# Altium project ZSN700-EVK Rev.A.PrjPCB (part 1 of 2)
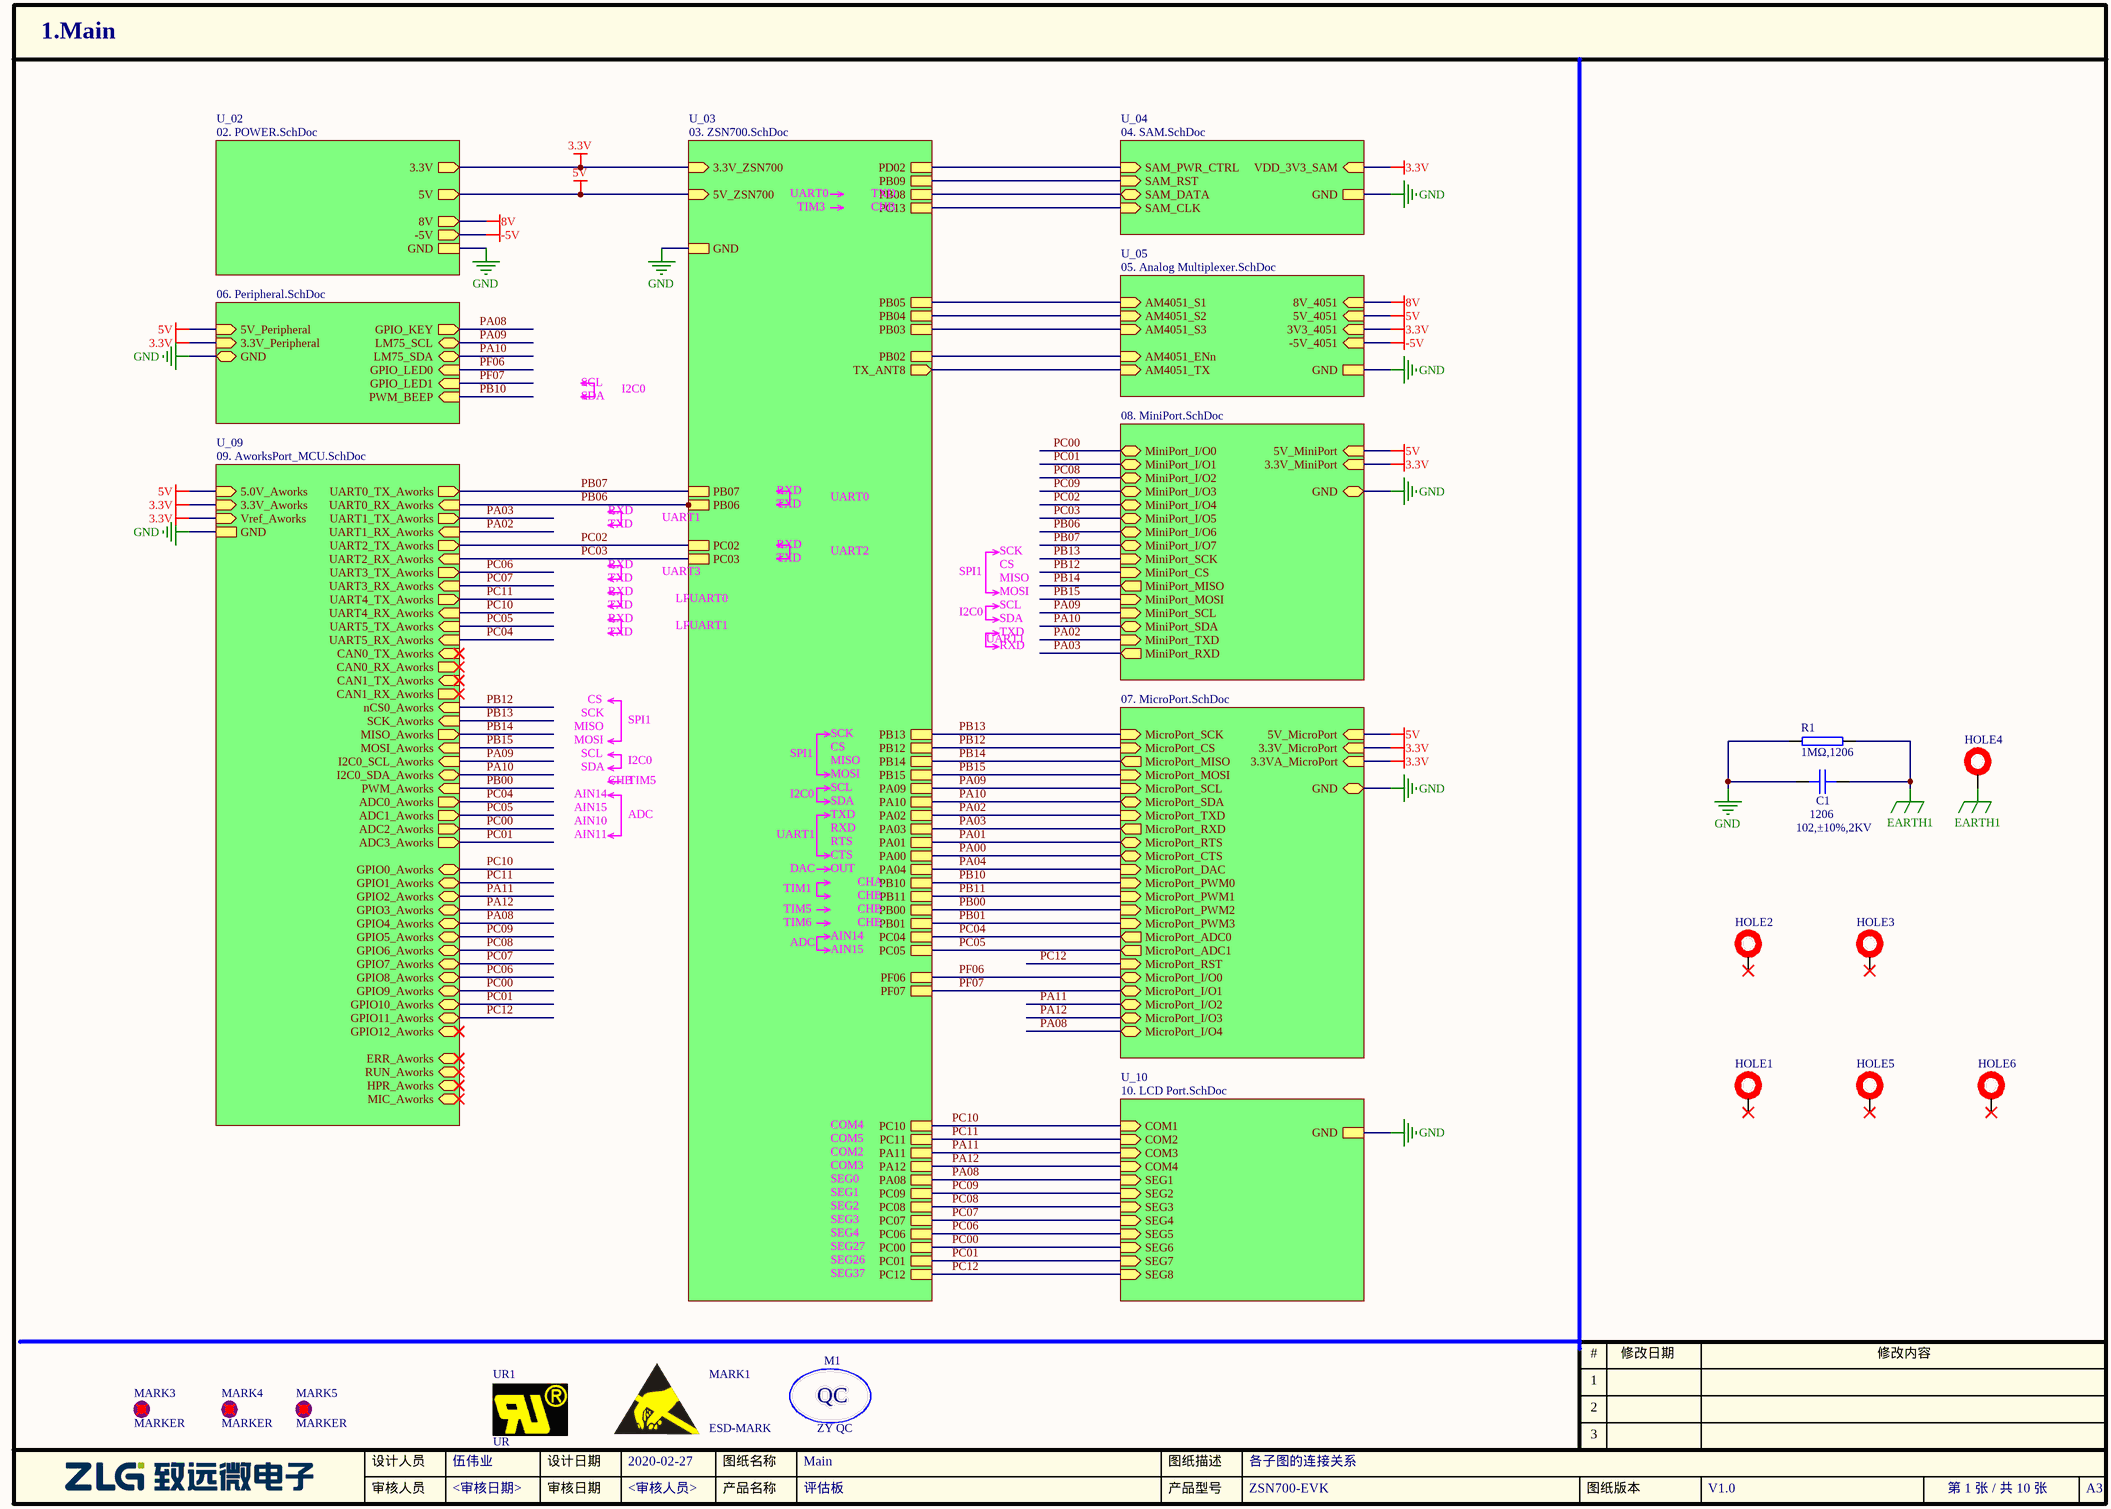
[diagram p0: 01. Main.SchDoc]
productModel: ZSN700-EVK; productName: 评估板
10 sheets, 172 parts. Net scope: hierarchical (ports join the sheet entries above them; power ports are global).
Board file: ZSN700-EVK Rev.A.PcbDoc
Sheets:
  01. Main.SchDoc
    U_03 = 06. Peripheral.SchDoc
    U_05 = 08. MiniPort.SchDoc
    U_06 = 07. MicroPort.SchDoc
    U_03 = 03. ZSN700.SchDoc
    U_02 = 02. POWER.SchDoc
    U_04 = 04. SAM.SchDoc
    U_05 = 05. Analog Multiplexer.SchDoc
    U_10 = 10. LCD Port.SchDoc
    U_09 = 09. AworksPort_MCU.SchDoc

## Sheet 01. Main.SchDoc
size A3; CheckedBy: <审核日期>; Author: 伍伟业; CompanyName: 广州立功科技股份有限公司; DocumentNumber: 1; SheetNumber: 1; SheetTotal: 10; PageSetup: Record=PageOptions¦CenterHorizontal=True¦CenterVertical=True¦PrintScale=1.00¦XCorrection=1.00¦YCorrection=1.00¦PrintKind=0¦BorderSize=5000000¦LeftOffset=0¦BottomOffset=0¦Orientation=2¦PaperLength=1000¦PaperWidth=1000¦Scale=100¦PaperSource=7¦PrintQuality=600¦MediaType=1¦DitherType=10¦PaperKind=A4¦PrintScaleMode=1; DesignDate: 2020-02-27; CheckDate: <审核人员>; SheetName: Main; SheetVersion: V1.0; SheetDescription: 各子图的连接关系

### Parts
C1  封装: 1206  型号: 102,±10%,2KV  [1206C]  (hidden comment: CC1206KKX7RDBB102,102)
HOLE1  (no value)  [HOLE-2.2]  (no BOM)
HOLE2  (no value)  [HOLE-2.2]  (no BOM)
HOLE3  (no value)  [HOLE-2.2]  (no BOM)
HOLE4  (no value)  [HOLE-2.2]  (no BOM)
HOLE5  (no value)  [HOLE-2.2]  (no BOM)
HOLE6  (no value)  [HOLE-2.2]  (no BOM)
M1  ZY QC  [ZY_QC]  (no BOM)
MARK1  ESD-MARK  [ZY_ESD-7]
MARK3  MARKER  [MARKER-C-1.0M]
MARK4  MARKER  [MARKER-C-1.0M]
MARK5  MARKER  [MARKER-C-1.0M]
R1  1MΩ,1206  [1206R]
UR1  UR  [ZY_UR-3X2]

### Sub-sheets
U_02 = 02. POWER.SchDoc: GND, 3.3V (out), 5V (out), 8V (out), -5V (out)
U_03 = 06. Peripheral.SchDoc: GPIO_LED0 (in), GPIO_LED1 (in), PWM_BEEP (in), GPIO_KEY (out), LM75_SCL (bidir), LM75_SDA (bidir), 5V_Peripheral (in), 3.3V_Peripheral (in), GND
U_03 = 03. ZSN700.SchDoc: PC13, PC00, PC01, PC02, PC03, PA00, PA01, PA02, PA03, PA04, PC04, PC05, PB00, PB01, PB02, PB10, PB11, PC08, PC07, PC06, PB15, PB14, PB13, PB12, PA12, PA11, PA10, PA09, PA08, PC09, PC12, PC11, PC10, PF07, PF06, PB07, PB06, PB05, PB04, PB03, PD02, PB08, PB09, 3.3V_ZSN700 (in), GND, TX_ANT8 (out), 5V_ZSN700 (in)
U_04 = 04. SAM.SchDoc: SAM_CLK (in), SAM_DATA (bidir), SAM_RST (in), SAM_PWR_CTRL (in), VDD_3V3_SAM (in), GND
U_05 = 08. MiniPort.SchDoc: MiniPort_SDA (bidir), MiniPort_SCL (in), MiniPort_MOSI (in), MiniPort_SCK (in), MiniPort_I/O3 (bidir), MiniPort_MISO (out), MiniPort_CS (in), MiniPort_I/O0 (bidir), MiniPort_I/O7 (bidir), MiniPort_I/O6 (bidir), MiniPort_I/O5 (bidir), MiniPort_I/O4 (bidir), MiniPort_TXD (in), MiniPort_RXD (out), MiniPort_I/O2 (bidir), MiniPort_I/O1 (bidir), GND, 3.3V_MiniPort (in), 5V_MiniPort (in)
U_05 = 05. Analog Multiplexer.SchDoc: AM4051_S2 (in), AM4051_S1 (in), AM4051_S3 (in), GND, 8V_4051 (in), AM4051_ENn (in), AM4051_TX (in), 3V3_4051 (in), 5V_4051 (in), -5V_4051 (in)
U_06 = 07. MicroPort.SchDoc: MicroPort_RXD (out), MicroPort_TXD (in), MicroPort_CTS (bidir), MicroPort_RTS (bidir), MicroPort_I/O0 (bidir), MicroPort_PWM1 (in), MicroPort_PWM0 (in), MicroPort_RST (in), MicroPort_SCK (in), MicroPort_MISO (out), MicroPort_MOSI (in), MicroPort_CS (in), MicroPort_I/O1 (bidir), MicroPort_PWM3 (in), MicroPort_PWM2 (in), MicroPort_ADC0 (out), MicroPort_ADC1 (out), MicroPort_DAC (in), MicroPort_I/O4 (bidir), MicroPort_SDA (bidir), MicroPort_SCL (in), MicroPort_I/O2 (bidir), MicroPort_I/O3 (bidir), GND, 3.3V_MicroPort (in), 5V_MicroPort (in), 3.3VA_MicroPort (in)
U_09 = 09. AworksPort_MCU.SchDoc: 3.3V_Aworks (in), 5.0V_Aworks (in), GND, Vref_Aworks (in), SCK_Aworks (in), MISO_Aworks (out), RUN_Aworks (bidir), CAN1_RX_Aworks (out), CAN0_RX_Aworks (out), nCS0_Aworks (in), MOSI_Aworks (in), ERR_Aworks (bidir), UART0_TX_Aworks (out), CAN1_TX_Aworks (in), CAN0_TX_Aworks (in), UART1_TX_Aworks (out), UART2_TX_Aworks (out), UART3_TX_Aworks (out), UART4_TX_Aworks (out), UART5_TX_Aworks (in), UART0_RX_Aworks (in), UART1_RX_Aworks (in), UART2_RX_Aworks (in), UART3_RX_Aworks (in), UART4_RX_Aworks (in), UART5_RX_Aworks (in), HPR_Aworks (bidir), MIC_Aworks (bidir), ADC0_Aworks (out), ADC1_Aworks (out), ADC2_Aworks (out), ADC3_Aworks (out), I2C0_SCL_Aworks (in), I2C0_SDA_Aworks (bidir), GPIO0_Aworks (bidir), GPIO1_Aworks (bidir), GPIO2_Aworks (bidir), GPIO3_Aworks (bidir), GPIO4_Aworks (bidir), GPIO5_Aworks (bidir), GPIO6_Aworks (bidir), GPIO7_Aworks (bidir), GPIO8_Aworks (bidir), GPIO9_Aworks (bidir), GPIO10_Aworks (bidir), GPIO11_Aworks (bidir), GPIO12_Aworks (bidir), PWM_Aworks (in)
U_10 = 10. LCD Port.SchDoc: GND, COM1 (in), COM2 (in), COM3 (in), COM4 (in), SEG1 (in), SEG2 (in), SEG3 (in), SEG4 (in), SEG5 (in), SEG6 (in), SEG7 (in), SEG8 (in)

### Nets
3.3V: sheet U_03/3.3V_Peripheral, sheet U_05/3.3V_MiniPort, sheet U_06/3.3V_MicroPort, sheet U_06/3.3VA_MicroPort, sheet U_03/3.3V_ZSN700, sheet U_02/3.3V, sheet U_04/VDD_3V3_SAM, sheet U_05/3V3_4051, sheet U_09/3.3V_Aworks, sheet U_09/Vref_Aworks
5V: sheet U_03/5V_Peripheral, sheet U_05/5V_MiniPort, sheet U_06/5V_MicroPort, sheet U_03/5V_ZSN700, sheet U_02/5V, sheet U_05/5V_4051, sheet U_09/5.0V_Aworks  [project net 5.0V_Aworks]
8V: sheet U_02/8V, sheet U_05/8V_4051
-5V: sheet U_02/-5V, sheet U_05/-5V_4051
EARTH1: C1.1 HOLE4.1 R1.2
GND: C1.2 R1.1 ; sheet U_03/GND, sheet U_05/GND, sheet U_06/GND, sheet U_03/GND, sheet U_02/GND, sheet U_04/GND, sheet U_05/GND, sheet U_10/GND, sheet U_09/GND
AM4051_ENn: sheet U_03/PB02, sheet U_05/AM4051_ENn
AM4051_S1: sheet U_03/PB05, sheet U_05/AM4051_S1
AM4051_S2: sheet U_03/PB04, sheet U_05/AM4051_S2
AM4051_S3: sheet U_03/PB03, sheet U_05/AM4051_S3
AM4051_TX: sheet U_03/TX_ANT8, sheet U_05/AM4051_TX
PA00: sheet U_06/MicroPort_CTS, sheet U_03/PA00  [project net MicroPort_CTS]
PA01: sheet U_06/MicroPort_RTS, sheet U_03/PA01  [project net MicroPort_RTS]
PA02: sheet U_05/MiniPort_TXD, sheet U_06/MicroPort_TXD, sheet U_03/PA02, sheet U_09/UART1_RX_Aworks  [project net MicroPort_TXD]
PA03: sheet U_05/MiniPort_RXD, sheet U_06/MicroPort_RXD, sheet U_03/PA03, sheet U_09/UART1_TX_Aworks  [project net MicroPort_RXD]
PA04: sheet U_06/MicroPort_DAC, sheet U_03/PA04  [project net MicroPort_DAC]
PA08: sheet U_03/GPIO_KEY, sheet U_06/MicroPort_I/O4, sheet U_03/PA08, sheet U_10/SEG1, sheet U_09/GPIO4_Aworks  [project net GPIO4_Aworks]
PA09: sheet U_03/LM75_SCL, sheet U_05/MiniPort_SCL, sheet U_06/MicroPort_SCL, sheet U_03/PA09, sheet U_09/I2C0_SCL_Aworks  [project net I2C0_SCL_Aworks]
PA10: sheet U_03/LM75_SDA, sheet U_05/MiniPort_SDA, sheet U_06/MicroPort_SDA, sheet U_03/PA10, sheet U_09/I2C0_SDA_Aworks  [project net I2C0_SDA_Aworks]
PA11: sheet U_06/MicroPort_I/O2, sheet U_03/PA11, sheet U_10/COM3, sheet U_09/GPIO2_Aworks  [project net COM2]
PA12: sheet U_06/MicroPort_I/O3, sheet U_03/PA12, sheet U_10/COM4, sheet U_09/GPIO3_Aworks  [project net COM3]
PB00: sheet U_06/MicroPort_PWM2, sheet U_03/PB00, sheet U_09/PWM_Aworks  [project net MicroPort_PWM2]
PB01: sheet U_06/MicroPort_PWM3, sheet U_03/PB01  [project net MicroPort_PWM3]
PB06: sheet U_05/MiniPort_I/O6, sheet U_03/PB06, sheet U_09/UART0_RX_Aworks  [project net MiniPort_I/O6]
PB07: sheet U_05/MiniPort_I/O7, sheet U_03/PB07, sheet U_09/UART0_TX_Aworks  [project net MiniPort_I/O7]
PB08: sheet U_03/PB08, sheet U_04/SAM_DATA
PB09: sheet U_03/PB09, sheet U_04/SAM_RST
PB10: sheet U_03/PWM_BEEP, sheet U_06/MicroPort_PWM0, sheet U_03/PB10  [project net MicroPort_PWM0]
PB11: sheet U_06/MicroPort_PWM1, sheet U_03/PB11  [project net MicroPort_PWM1]
PB12: sheet U_05/MiniPort_CS, sheet U_06/MicroPort_CS, sheet U_03/PB12, sheet U_09/nCS0_Aworks  [project net MicroPort_CS]
PB13: sheet U_05/MiniPort_SCK, sheet U_06/MicroPort_SCK, sheet U_03/PB13, sheet U_09/SCK_Aworks  [project net MicroPort_SCK]
PB14: sheet U_05/MiniPort_MISO, sheet U_06/MicroPort_MISO, sheet U_03/PB14, sheet U_09/MISO_Aworks  [project net MicroPort_MISO]
PB15: sheet U_05/MiniPort_MOSI, sheet U_06/MicroPort_MOSI, sheet U_03/PB15, sheet U_09/MOSI_Aworks  [project net MicroPort_MOSI]
PC00: sheet U_05/MiniPort_I/O0, sheet U_03/PC00, sheet U_10/SEG6, sheet U_09/ADC2_Aworks, sheet U_09/GPIO9_Aworks  [project net ADC2_Aworks]
PC01: sheet U_05/MiniPort_I/O1, sheet U_03/PC01, sheet U_10/SEG7, sheet U_09/ADC3_Aworks, sheet U_09/GPIO10_Aworks  [project net ADC3_Aworks]
PC02: sheet U_05/MiniPort_I/O4, sheet U_03/PC02, sheet U_09/UART2_TX_Aworks  [project net MiniPort_I/O4]
PC03: sheet U_05/MiniPort_I/O5, sheet U_03/PC03, sheet U_09/UART2_RX_Aworks  [project net MiniPort_I/O5]
PC04: sheet U_06/MicroPort_ADC0, sheet U_03/PC04, sheet U_09/UART5_RX_Aworks, sheet U_09/ADC0_Aworks  [project net ADC0_Aworks]
PC05: sheet U_06/MicroPort_ADC1, sheet U_03/PC05, sheet U_09/UART5_TX_Aworks, sheet U_09/ADC1_Aworks  [project net ADC1_Aworks]
PC06: sheet U_03/PC06, sheet U_10/SEG5, sheet U_09/UART3_TX_Aworks, sheet U_09/GPIO8_Aworks  [project net GPIO8_Aworks]
PC07: sheet U_03/PC07, sheet U_10/SEG4, sheet U_09/UART3_RX_Aworks, sheet U_09/GPIO7_Aworks  [project net GPIO7_Aworks]
PC08: sheet U_05/MiniPort_I/O2, sheet U_03/PC08, sheet U_10/SEG3, sheet U_09/GPIO6_Aworks  [project net GPIO6_Aworks]
PC09: sheet U_05/MiniPort_I/O3, sheet U_03/PC09, sheet U_10/SEG2, sheet U_09/GPIO5_Aworks  [project net GPIO5_Aworks]
PC10: sheet U_03/PC10, sheet U_10/COM1, sheet U_09/UART4_RX_Aworks, sheet U_09/GPIO0_Aworks  [project net COM0]
PC11: sheet U_03/PC11, sheet U_10/COM2, sheet U_09/UART4_TX_Aworks, sheet U_09/GPIO1_Aworks  [project net COM1]
PC12: sheet U_06/MicroPort_RST, sheet U_03/PC12, sheet U_10/SEG8, sheet U_09/GPIO11_Aworks  [project net GPIO11_Aworks]
PC13: sheet U_03/PC13, sheet U_04/SAM_CLK
PD02: sheet U_03/PD02, sheet U_04/SAM_PWR_CTRL
PF06: sheet U_03/GPIO_LED0, sheet U_06/MicroPort_I/O0, sheet U_03/PF06  [project net GPIO_LED0]
PF07: sheet U_03/GPIO_LED1, sheet U_06/MicroPort_I/O1, sheet U_03/PF07  [project net GPIO_LED1]

Not connected (* = marked no-connect by the designer): HOLE1 1*; HOLE2 1*; HOLE3 1*; HOLE5 1*; HOLE6 1*; MARK3 0*; MARK4 0*; MARK5 0*

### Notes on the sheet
- UART0
- TIM3
- CHB
- TXD
- SDA
- SCL
- I2C0
- RXD
- UART1
- UART3
- UART2
- SPI1
- MISO
- CS
- SCK
- LPUART0
- LPUART1
- MOSI
- TIM5
- AIN14
- AIN15
- AIN10
- AIN11
- ADC
- RTS
- CTS
- TIM1
- DAC
- OUT
- CHA
- TIM6
- COM4
- COM5
- COM2
- COM3
- SEG0
- SEG1
- SEG2
- SEG3
- SEG4
- SEG27
- SEG26
- SEG37

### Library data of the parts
C1 = 1.02.03.0003: CC1206KKX7RDBB102,102,±10%,2KV,X7R,1206,YAGEO,RoHS; 名称: 电容; 设备封装名称: C1206_102_X7R_2KV_10%; 贴片和直插: SMT; 器件优选方案: 正常状态，可以选用
HOLE1-HOLE6 = HOLE - 不上螺丝
R1 = 1.01.03.0019: 1MΩ,1206,RoHS; 名称: 电阻; 封装: 1206; 设备封装名称: R1206_1M; 厂商: Ralec; 贴片和直插: SMT; 器件优选方案: 正常状态，可以选用

## Sheet 06. Peripheral.SchDoc
size A4; CompanyName: 广州立功科技股份有限公司; DocumentNumber: 6; SheetNumber: 6; SheetTotal: 10; PageSetup: Record=PageOptions¦CenterHorizontal=True¦CenterVertical=True¦PrintScale=1.00¦XCorrection=1.00¦YCorrection=1.00¦PrintKind=0¦BorderSize=5000000¦LeftOffset=0¦BottomOffset=0¦Orientation=2¦PaperLength=1000¦PaperWidth=1000¦Scale=100¦PaperSource=7¦PrintQuality=600¦MediaType=1¦DitherType=10¦PaperKind=A4¦PrintScaleMode=1; DesignDate: 2019.10; CheckDate: 2019.10; SheetName: Peripheral; SheetVersion: Rev.A; SheetDescription: 外设子图
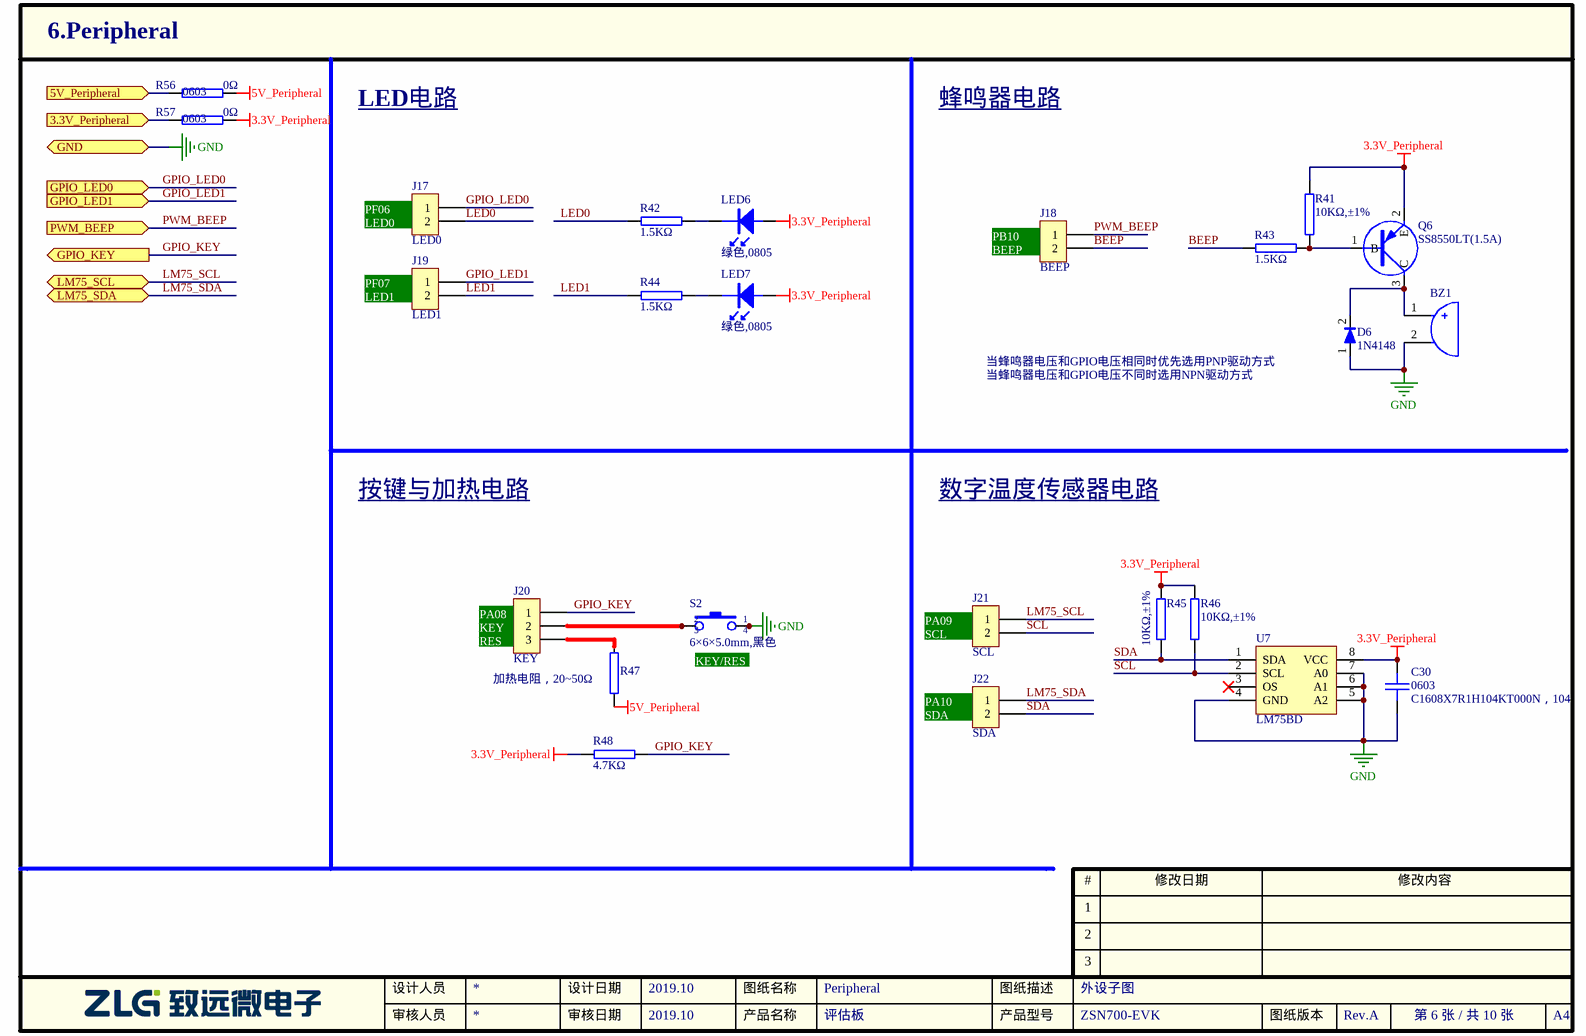
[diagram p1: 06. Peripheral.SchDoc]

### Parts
BZ1  BUZZER2  [BUZZ-4/9]  (value not drawn)
C30  封装: 0603  [0603C]  (hidden comment: C1608X7R1H104KT000N，104)
D6  value 1N4148  [SOD-323]  (hidden comment: DIODE1)
J17  LED0  [SIP-2-2.54]
J18  BEEP  [SIP-2-2.54]
J19  LED1  [SIP-2-2.54]
J20  KEY  [SIP-3-2.54]
J21  SCL  [SIP-2-2.54]
J22  SDA  [SIP-2-2.54]
LED6  value 绿色,0805  [LED-0805]  (hidden comment: LED0)
LED7  value 绿色,0805  [LED-0805]  (hidden comment: LED1)
Q6  value SS8550LT(1.5A)  [SOT-23]  (hidden comment: PNP-1)
R41  10KΩ,±1%  [0603R]
R42  1.5KΩ  [0603R]
R43  1.5KΩ  [0603R]
R44  1.5KΩ  [0603R]
R45  10KΩ,±1%  [0603R]
R46  10KΩ,±1%  [0603R]
R47  20Ω,±5%  [RESAD1778W80L1450D430P]  (value not drawn)
R48  4.7KΩ  [0603R]
R56  封装: 0603  [0603R]  (hidden comment: 0Ω)
R57  封装: 0603  [0603R]  (hidden comment: 0Ω)
S2  value 6×6×5.0mm,黑色  [KEY-6S]  (hidden comment: KEY/RES)
U7  value LM75BD  [SOIC127P600X175-8N]  (hidden comment: LM75B)

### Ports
3.3V_Peripheral (in), 5V_Peripheral (in), GND, GPIO_KEY (out), GPIO_LED0 (in), GPIO_LED1 (in), LM75_SCL (bidir), LM75_SDA (bidir), PWM_BEEP (in)

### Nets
3.3V: R57.1 ; port 3.3V_Peripheral
3.3V_Peripheral: C30.1 LED6.1 LED7.1 Q6.2(E) R41.2 R45.2 R46.2 R48.2 R57.2 U7.8(VCC)
5.0V_Aworks: R56.1 ; port 5V_Peripheral
5V_Peripheral: R47.1 R56.2
GND: BZ1.2(B) C30.2 D6.1 S2.1 S2.4 U7.4(GND) U7.5(A2) U7.6(A1) U7.7(A0) ; port GND
BEEP: J18.2 R43.1
GPIO_KEY: J20.1 R48.1 ; port GPIO_KEY  [project net GPIO4_Aworks]
GPIO_LED0: J17.1 ; port GPIO_LED0
GPIO_LED1: J19.1 ; port GPIO_LED1
LED0: J17.2 R42.2
LED1: J19.2 R44.2
LM75_SCL: J21.1 ; port LM75_SCL  [project net I2C0_SCL_Aworks]
LM75_SDA: J22.1 ; port LM75_SDA  [project net I2C0_SDA_Aworks]
PWM_BEEP: J18.1 ; port PWM_BEEP  [project net MicroPort_PWM0]
SCL: J21.2 R46.1 U7.2(SCL)
SDA: J22.2 R45.1 U7.1(SDA)
NetBZ1_1: BZ1.1(A) D6.2 Q6.3(C)
NetJ20_2: J20.2 S2.2 S2.3
NetJ20_3: J20.3 R47.2
NetLED6_2: LED6.2 R42.1
NetLED7_2: LED7.2 R44.1
NetQ6_1: Q6.1(B) R41.1 R43.2

Not connected (* = marked no-connect by the designer): U7 3(OS)*

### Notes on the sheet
- LED电路
- 蜂鸣器电路
- (near J17) LED0
- (near J17) PF06
- (near J18) PB10
- (near J18) BEEP
- (near J19) LED1
- (near J19) PF07
- 当蜂鸣器电压和GPIO电压不同时选用NPN驱动方式
- 当蜂鸣器电压和GPIO电压相同时优先选用PNP驱动方式
- 按键与加热电路
- 数字温度传感器电路
- (near J20) RES
- (near J20) KEY
- (near J20) PA08
- (near J21) PA09
- (near J21) SCL
- 加热电阻，20~50Ω
- (near S2) KEY/RES
- (near J22) PA10
- (near J22) SDA

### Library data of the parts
BZ1 = 1.06.09.0016: Buzzer有极性; Value: AS-905I-LF,无源; 名称: 讯响器; 厂商: 常州笠翔; 型号: AS-905I-LF,无源,Ф9×4.8mm; 贴片和直插: THT; PCB备注: Flq-Shcj-Twrj-150113; 器件优选方案: 量产物料,优先选用
C30 = 1.02.01.0072: C1608X7R1H104KT000N，104，±10%，50V，X7R,TDK,0603,RoHS; 名称: 电容; 贴片和直插: SMT; PCB备注: 151110lmd; 器件优选方案: 正常状态，可以选用
D6 = 1.04.07.0027: 1N4148,SOD-323,RoHS; 名称: 二极管; 设备封装名称: SOD-323_1N4148; 贴片和直插: SMT
J17-J19 J21 J22 = CON2: Connector; 物料代码: 1.10.03.0164
J20 = CON3: Connector; 物料代码: 1.10.03.0164
LED6 LED7 = 1.04.05.0002: 绿色,0805,0805,RoHS; 名称: 发光二极管; 封装: 0805; 设备封装名称: LED0805-GREEN; 贴片和直插: SMT; 器件优选方案: 样品物料,谨慎选用
Q6 = 1.04.09.0002: PNP Transistor; 名称: 三极管; 设备封装名称: SOT-23_SS8550LT; 厂商: 江苏长电; 贴片和直插: SMT
R41 = 1.01.01.0052: 10KΩ,±1%,0603,*,RoHS; 名称: 电阻; 封装: 0603; 设备封装名称: R0603_10K_1%; 厂商: Ralec; 贴片和直插: SMT
R42 R44 = 1.01.01.0037: 1.5KΩ,0603,*,RoHS; 名称: 电阻; 封装: 0603; 设备封装名称: R0603_1.5K; 厂商: Ralec; 贴片和直插: SMT; 器件优选方案: 正常状态，可以选用
R43 = 1.01.01.0037: 1.5KΩ,0603,*,RoHS; 名称: 电阻; 封装: 0603; 设备封装名称: R0603_1.5K; 厂商: Ralec; 贴片和直插: SMT; 器件优选方案: 状态正常
R45 R46 = 1.01.01.0052: 10KΩ,±1%,0603,*,RoHS; 名称: 电阻; 封装: 0603; 设备封装名称: R0603_10K_1%; 厂商: Ralec; 贴片和直插: SMT; 器件优选方案: 正常状态，可以选用
R47 = 1.01.10.0003: 20Ω,±5%,2W,Ф5.5×16mm,RoHS; 名称: 电阻; 贴片和直插: THT
R48 = 1.01.01.0045: 4.7KΩ,0603,*,RoHS; 名称: 电阻; 封装: 0603; 设备封装名称: R0603_4.7K; 厂商: Ralec; 贴片和直插: SMT; 器件优选方案: 正常状态，可以选用
R56 R57 = 1.01.01.0001: 0Ω,0603,*,RoHS; 名称: 电阻; 设备封装名称: R0603_0R; 厂商: Ralec; 贴片和直插: SMT; 器件优选方案: 正常状态，可以选用
S2 = 1.09.01.0003: 6×6×5.0mm,黑色,SMD,,*; 名称: 轻触按键; 贴片和直插: SMT
U7 = 1.05.10.0602: LM75BD,SO-9,NXP,RoHS; 名称: IC; 封装: SO-8; 贴片和直插: SMT; 器件优选方案: 样品物料,谨慎选用

## Sheet 08. MiniPort.SchDoc
size A4; CompanyName: 广州立功科技股份有限公司; DocumentNumber: 5; SheetNumber: 8; SheetTotal: 10; PageSetup: Record=PageOptions¦CenterHorizontal=True¦CenterVertical=True¦PrintScale=1.00¦XCorrection=1.00¦YCorrection=1.00¦PrintKind=0¦BorderSize=5000000¦LeftOffset=0¦BottomOffset=0¦Orientation=2¦PaperLength=1000¦PaperWidth=1000¦Scale=100¦PaperSource=7¦PrintQuality=600¦MediaType=1¦DitherType=10¦PaperKind=A4¦PrintScaleMode=1; DesignDate: 2019.10; CheckDate: 2019.10; SheetName: MiniPort; SheetVersion: Rev.A; SheetDescription: MiniPort接口子图
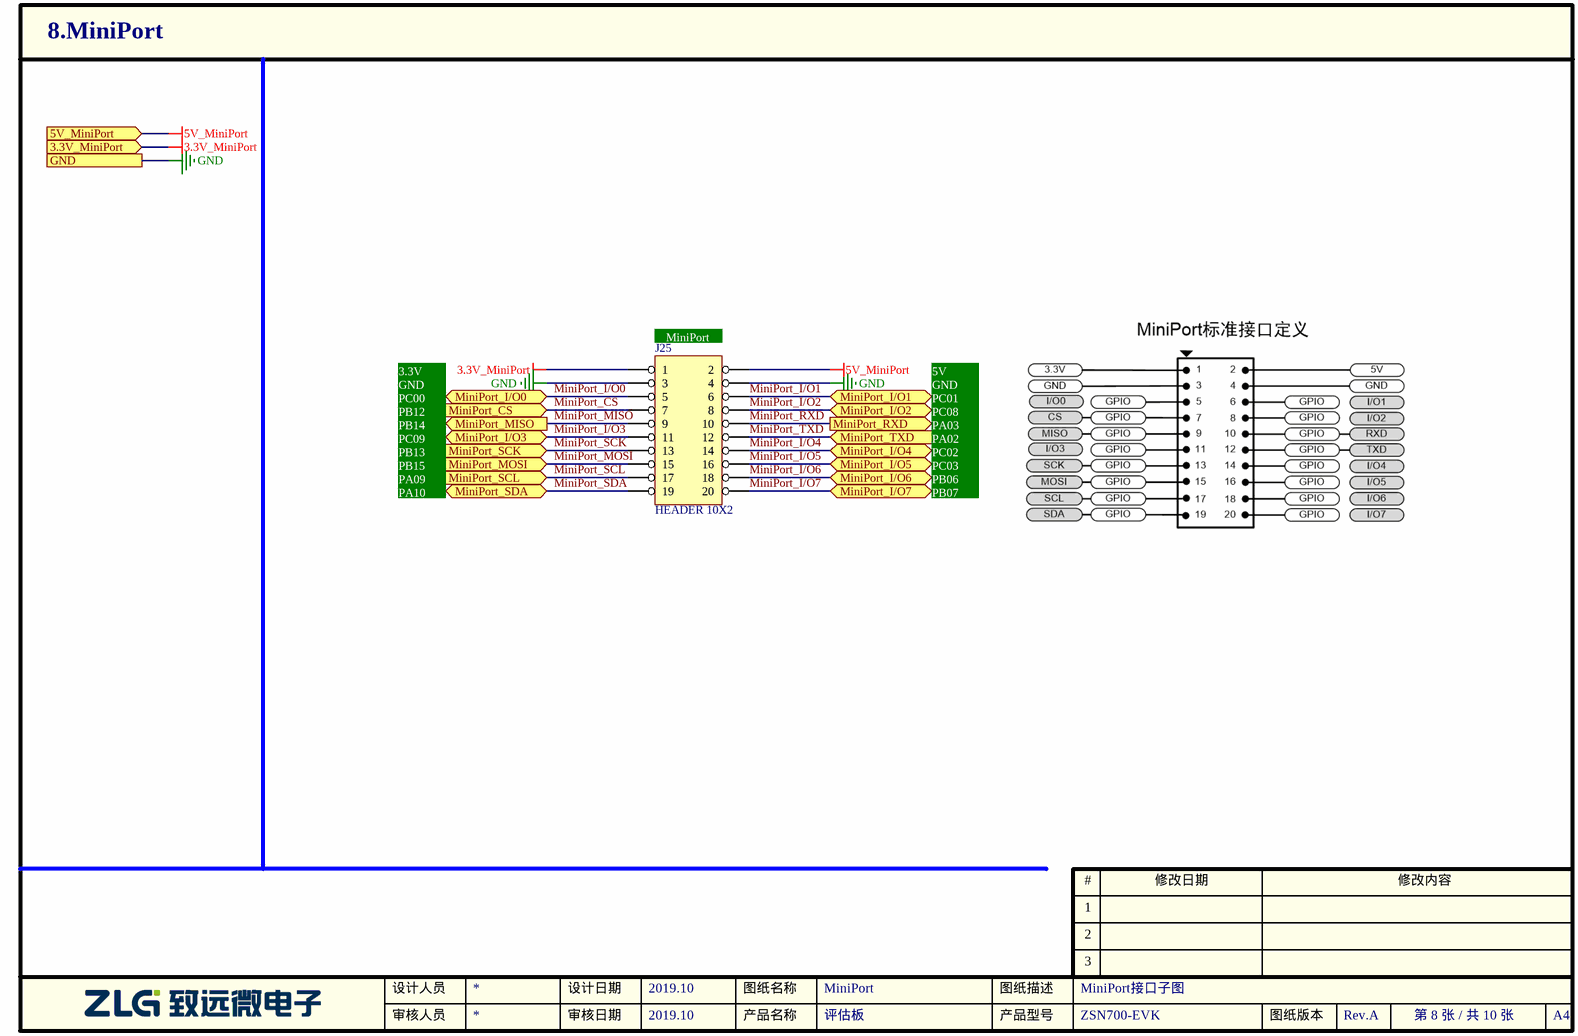
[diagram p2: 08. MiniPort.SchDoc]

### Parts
J25  HEADER 10X2  [IDC-20-2.54-R90]

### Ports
3.3V_MiniPort (in), 5V_MiniPort (in), GND, MiniPort_CS (in), MiniPort_I/O0 (bidir), MiniPort_I/O1 (bidir), MiniPort_I/O2 (bidir), MiniPort_I/O3 (bidir), MiniPort_I/O4 (bidir), MiniPort_I/O5 (bidir), MiniPort_I/O6 (bidir), MiniPort_I/O7 (bidir), MiniPort_MISO (out), MiniPort_MOSI (in), MiniPort_RXD (out), MiniPort_SCK (in), MiniPort_SCL (in), MiniPort_SDA (bidir), MiniPort_TXD (in)

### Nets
3.3V_MiniPort: J25.1 ; port 3.3V_MiniPort  [project net 3.3V]
5V_MiniPort: J25.2 ; port 5V_MiniPort  [project net 5.0V_Aworks]
GND: J25.3 J25.4 ; port GND
MiniPort_CS: J25.7 ; port MiniPort_CS  [project net MicroPort_CS]
MiniPort_I/O0: J25.5 ; port MiniPort_I/O0  [project net ADC2_Aworks]
MiniPort_I/O1: J25.6 ; port MiniPort_I/O1  [project net ADC3_Aworks]
MiniPort_I/O2: J25.8 ; port MiniPort_I/O2  [project net GPIO6_Aworks]
MiniPort_I/O3: J25.11 ; port MiniPort_I/O3  [project net GPIO5_Aworks]
MiniPort_I/O4: J25.14 ; port MiniPort_I/O4
MiniPort_I/O5: J25.16 ; port MiniPort_I/O5
MiniPort_I/O6: J25.18 ; port MiniPort_I/O6
MiniPort_I/O7: J25.20 ; port MiniPort_I/O7
MiniPort_MISO: J25.9 ; port MiniPort_MISO  [project net MicroPort_MISO]
MiniPort_MOSI: J25.15 ; port MiniPort_MOSI  [project net MicroPort_MOSI]
MiniPort_RXD: J25.10 ; port MiniPort_RXD  [project net MicroPort_RXD]
MiniPort_SCK: J25.13 ; port MiniPort_SCK  [project net MicroPort_SCK]
MiniPort_SCL: J25.17 ; port MiniPort_SCL  [project net I2C0_SCL_Aworks]
MiniPort_SDA: J25.19 ; port MiniPort_SDA  [project net I2C0_SDA_Aworks]
MiniPort_TXD: J25.12 ; port MiniPort_TXD  [project net MicroPort_TXD]

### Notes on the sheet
- 3.3V
- GND
- (near J25) MiniPort
- 5V
- PC00
- PB12
- PB14
- PC09
- PC01
- PC08
- PA03
- PA02
- PB13
- PB15
- PA09
- PA10
- PC02
- PC03
- PB06
- PB07

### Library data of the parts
J25 = HEADER 10X2: 物料代码: 1.10.03.0016

## Sheet 07. MicroPort.SchDoc
size A4; CompanyName: 广州立功科技股份有限公司; DocumentNumber: 6; SheetNumber: 7; SheetTotal: 10; PageSetup: Record=PageOptions¦CenterHorizontal=True¦CenterVertical=True¦PrintScale=1.00¦XCorrection=1.00¦YCorrection=1.00¦PrintKind=0¦BorderSize=5000000¦LeftOffset=0¦BottomOffset=0¦Orientation=2¦PaperLength=1000¦PaperWidth=1000¦Scale=100¦PaperSource=7¦PrintQuality=600¦MediaType=1¦DitherType=10¦PaperKind=A4¦PrintScaleMode=1; DesignDate: 2019.10; CheckDate: 2019.10; SheetName: MicroPort; SheetVersion: Rev.A; SheetDescription: MicroPort子图
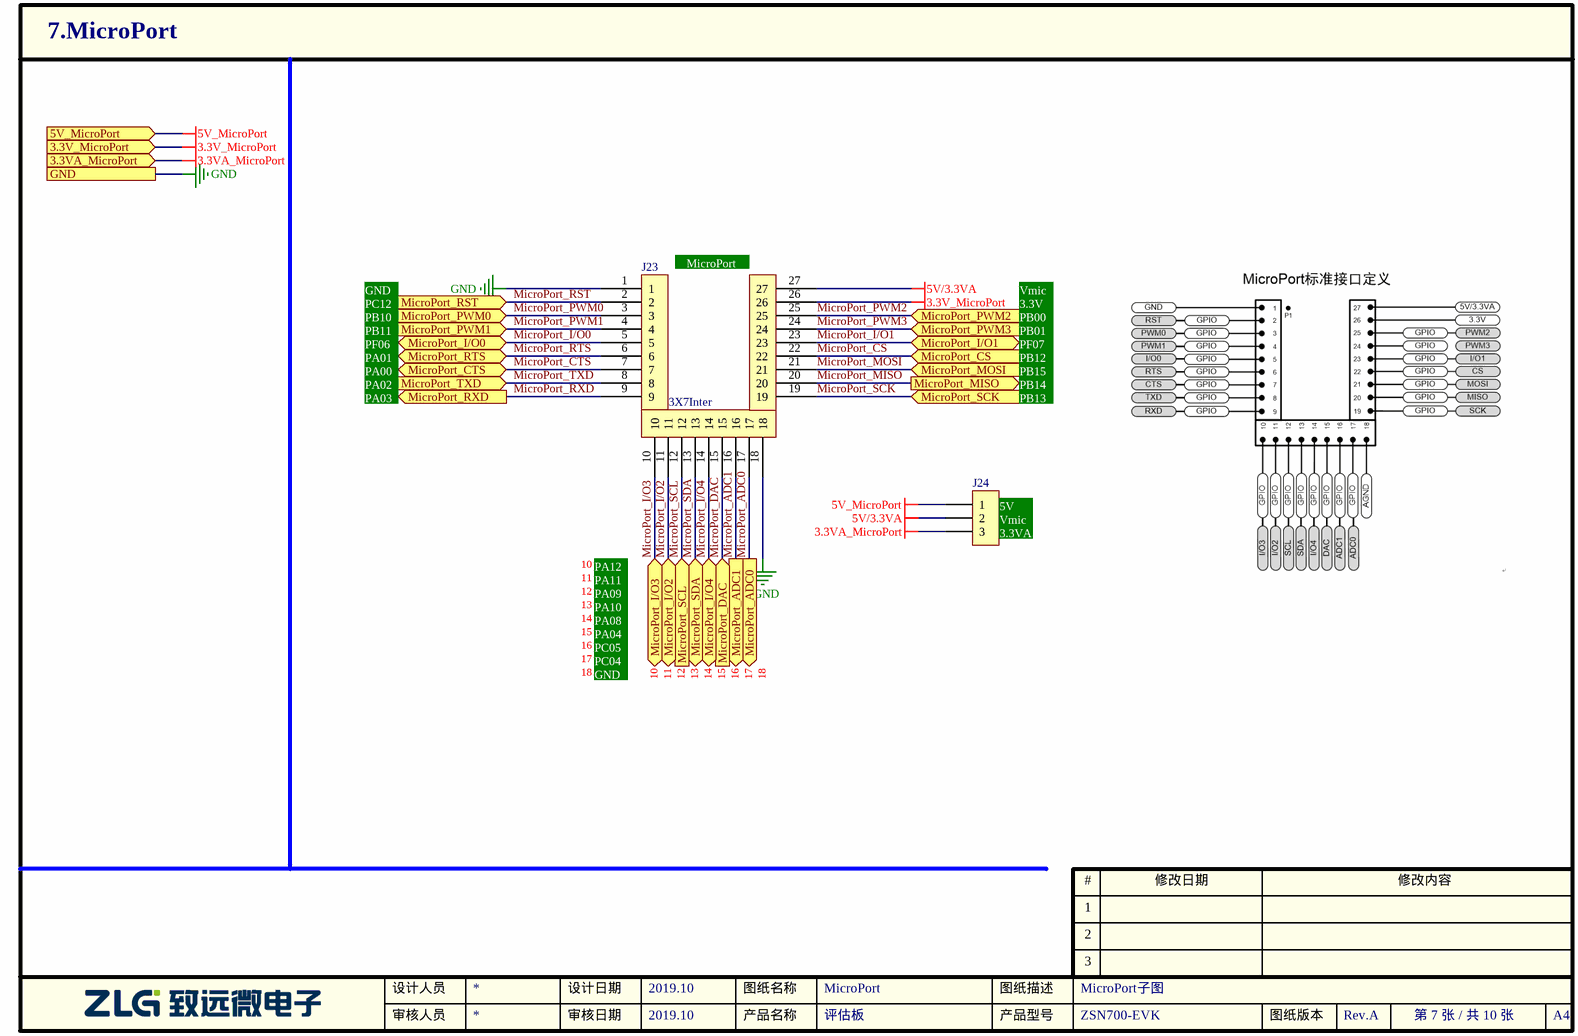
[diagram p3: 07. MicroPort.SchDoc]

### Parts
J23  3X7Inter  [SIP-27 2.54C]
J24  (no value)  [SIP-3-2.54]

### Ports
3.3V_MicroPort (in), 3.3VA_MicroPort (in), 5V_MicroPort (in), GND, MicroPort_ADC0 (out), MicroPort_ADC1 (out), MicroPort_CS (in), MicroPort_CTS (bidir), MicroPort_DAC (in), MicroPort_I/O0 (bidir), MicroPort_I/O1 (bidir), MicroPort_I/O2 (bidir), MicroPort_I/O3 (bidir), MicroPort_I/O4 (bidir), MicroPort_MISO (out), MicroPort_MOSI (in), MicroPort_PWM0 (in), MicroPort_PWM1 (in), MicroPort_PWM2 (in), MicroPort_PWM3 (in), MicroPort_RST (in), MicroPort_RTS (bidir), MicroPort_RXD (out), MicroPort_SCK (in), MicroPort_SCL (in), MicroPort_SDA (bidir), MicroPort_TXD (in)

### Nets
3.3V_MicroPort: J23.26 J24.3 ; port 3.3V_MicroPort, port 3.3VA_MicroPort  [also labelled 3.3VA_MicroPort]  [project net 3.3V]
5V/3.3VA: J23.27 J24.2
5V_MicroPort: J24.1 ; port 5V_MicroPort  [project net 5.0V_Aworks]
AGND: J23.18
GND: J23.1 ; port GND
MicroPort_ADC0: J23.17 ; port MicroPort_ADC0  [project net ADC0_Aworks]
MicroPort_ADC1: J23.16 ; port MicroPort_ADC1  [project net ADC1_Aworks]
MicroPort_CS: J23.22 ; port MicroPort_CS
MicroPort_CTS: J23.7 ; port MicroPort_CTS
MicroPort_DAC: J23.15 ; port MicroPort_DAC
MicroPort_I/O0: J23.5 ; port MicroPort_I/O0  [project net GPIO_LED0]
MicroPort_I/O1: J23.23 ; port MicroPort_I/O1  [project net GPIO_LED1]
MicroPort_I/O2: J23.11 ; port MicroPort_I/O2  [project net COM2]
MicroPort_I/O3: J23.10 ; port MicroPort_I/O3  [project net COM3]
MicroPort_I/O4: J23.14 ; port MicroPort_I/O4  [project net GPIO4_Aworks]
MicroPort_MISO: J23.20 ; port MicroPort_MISO
MicroPort_MOSI: J23.21 ; port MicroPort_MOSI
MicroPort_PWM0: J23.3 ; port MicroPort_PWM0
MicroPort_PWM1: J23.4 ; port MicroPort_PWM1
MicroPort_PWM2: J23.25 ; port MicroPort_PWM2
MicroPort_PWM3: J23.24 ; port MicroPort_PWM3
MicroPort_RST: J23.2 ; port MicroPort_RST  [project net GPIO11_Aworks]
MicroPort_RTS: J23.6 ; port MicroPort_RTS
MicroPort_RXD: J23.9 ; port MicroPort_RXD
MicroPort_SCK: J23.19 ; port MicroPort_SCK
MicroPort_SCL: J23.12 ; port MicroPort_SCL  [project net I2C0_SCL_Aworks]
MicroPort_SDA: J23.13 ; port MicroPort_SDA  [project net I2C0_SDA_Aworks]
MicroPort_TXD: J23.8 ; port MicroPort_TXD

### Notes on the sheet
- PC12
- GND
- (near J23) MicroPort
- 3.3V
- Vmic
- PA02
- PA01
- PA00
- PB11
- PF06
- PB10
- PB14
- PB12
- PB15
- PB01
- PF07
- PB00
- PA03
- PB13
- (near J24) 5V
- 10
- 11
- PA12
- PA11
- (near J24) Vmic
  3.3VA
- 12
- 13
- 14
- 15
- 16
- PA04
- PC05
- PA10
- PA08
- PA09
- 17
- 18
- PC04

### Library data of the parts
J23 = 3X7Inter: 物料代码: 1.10.11.0074
J24 = CON3: Connector; 物料代码: 1.10.03.0164

## Sheet 03. ZSN700.SchDoc
size A3; CheckedBy: <审核日期>; Author: 伍伟业; CompanyName: 广州立功科技股份有限公司; DocumentNumber: 3; SheetNumber: 3; SheetTotal: 10; PageSetup: Record=PageOptions¦CenterHorizontal=True¦CenterVertical=True¦PrintScale=1.00¦XCorrection=1.00¦YCorrection=1.00¦PrintKind=0¦BorderSize=5000000¦LeftOffset=0¦BottomOffset=0¦Orientation=2¦PaperLength=1000¦PaperWidth=1000¦Scale=100¦PaperSource=7¦PrintQuality=600¦MediaType=1¦DitherType=10¦PaperKind=A4¦PrintScaleMode=1; DesignDate: 202-02-25; CheckDate: <审核人员>; SheetName: ZSN700; SheetVersion: V1.0; SheetDescription: ZSN700最小系统
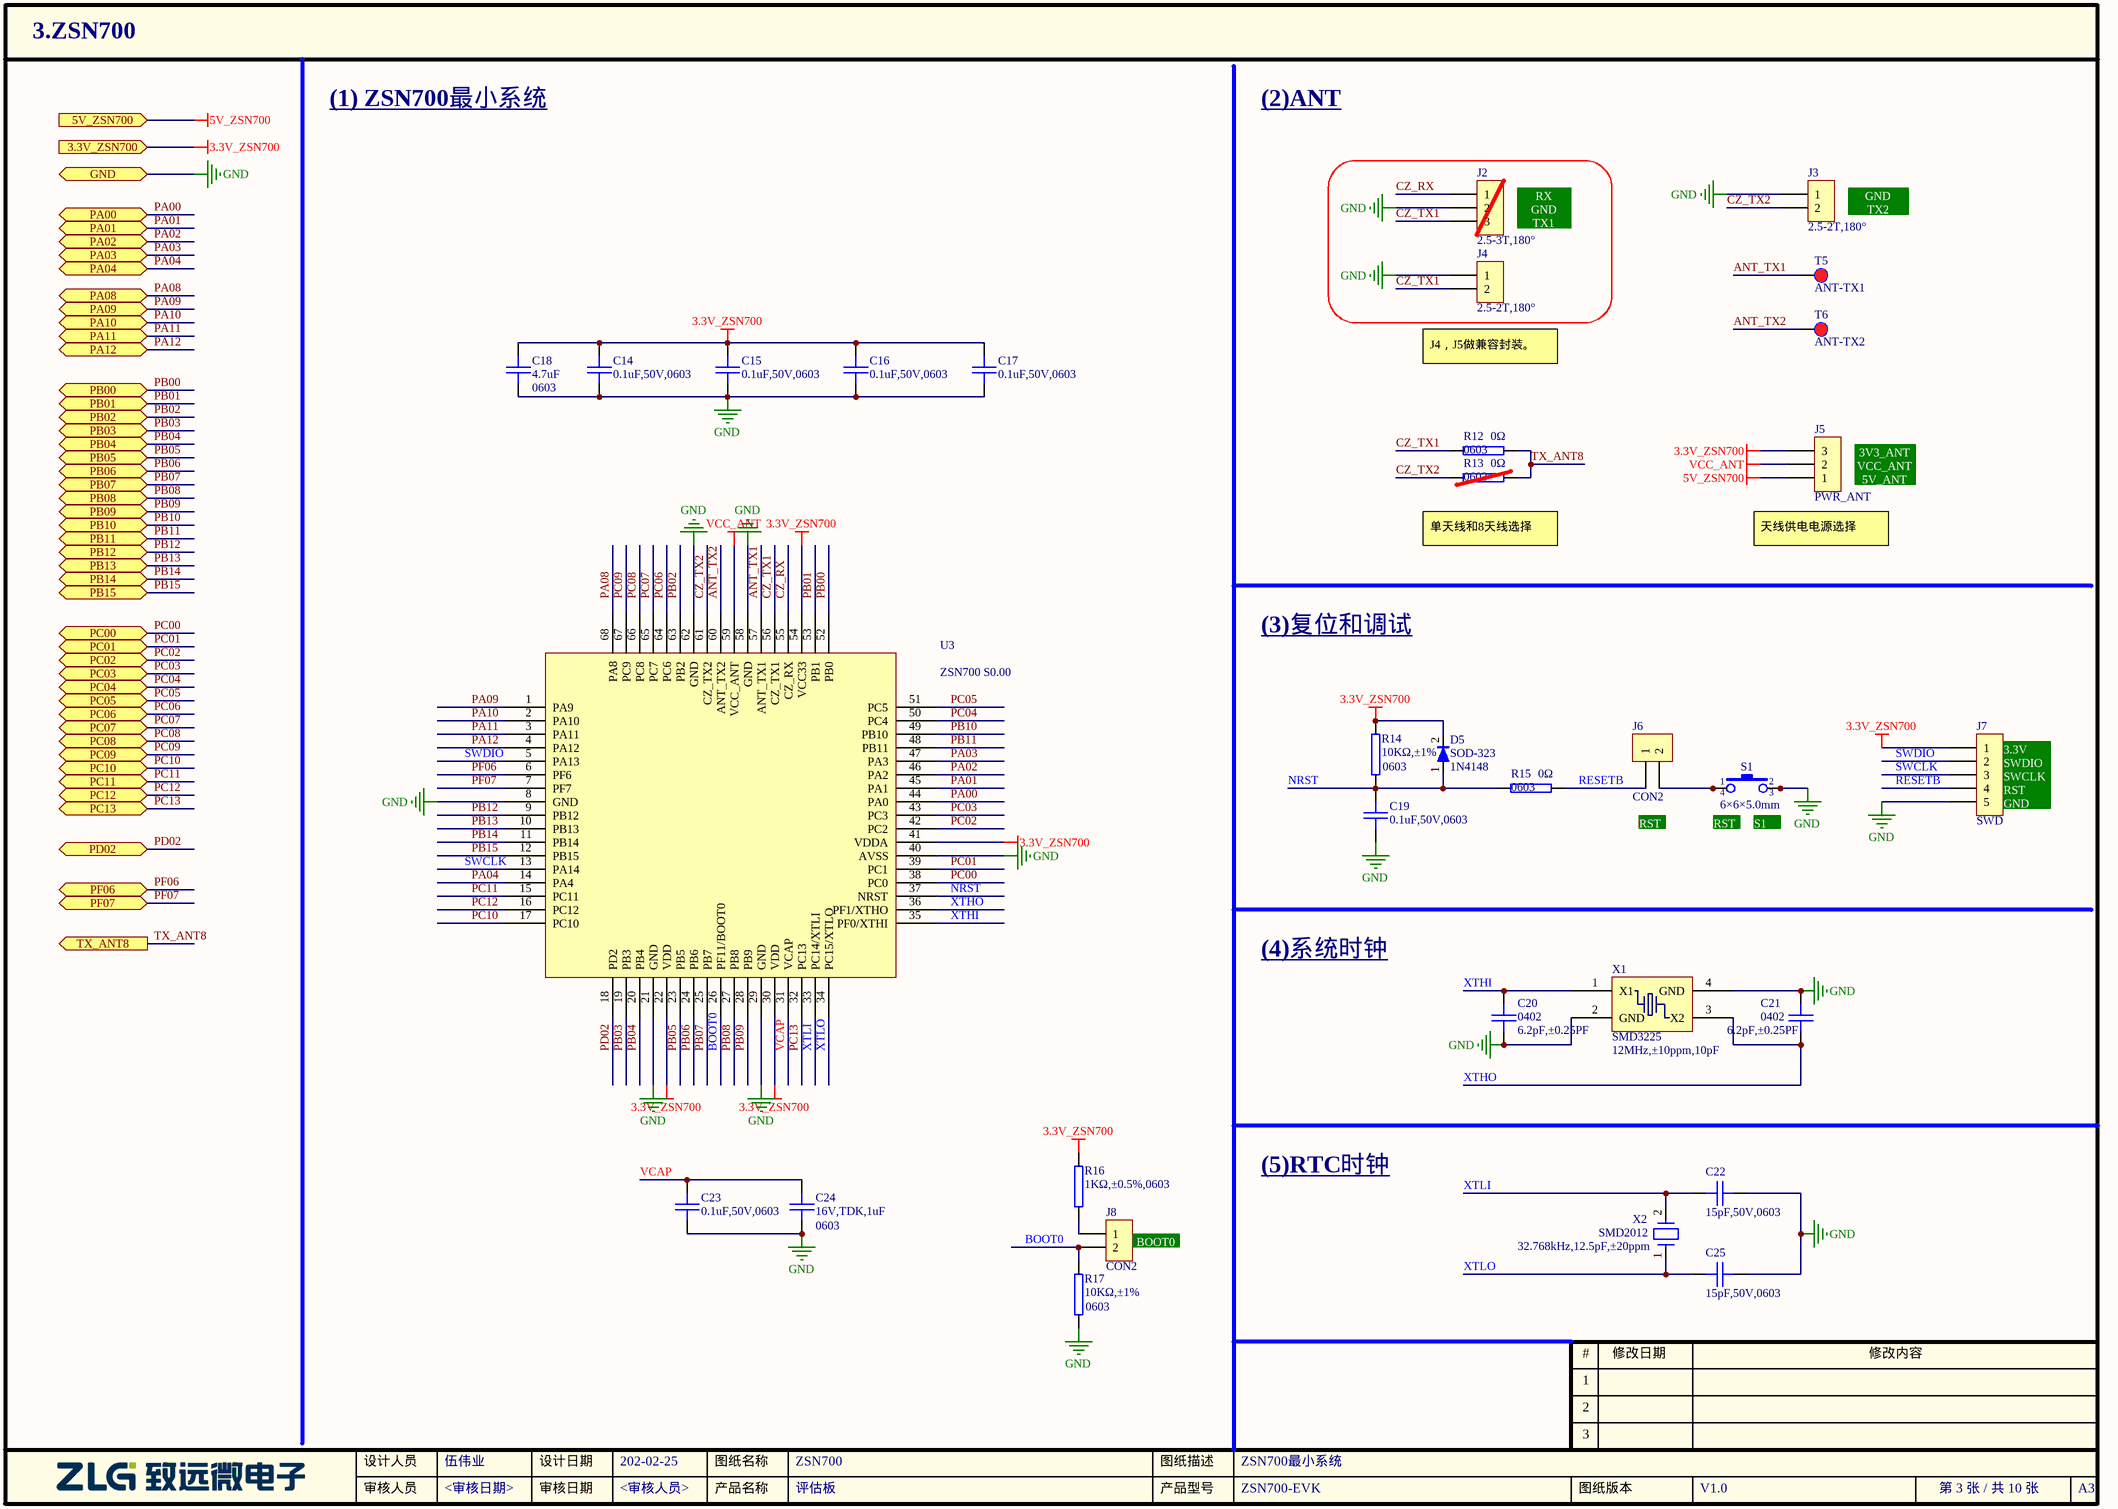
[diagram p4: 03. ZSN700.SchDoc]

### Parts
C14  0.1uF,50V,0603  [0603C]
C15  0.1uF,50V,0603  [0603C]
C16  0.1uF,50V,0603  [0603C]
C17  0.1uF,50V,0603  [0603C]
C18  封装: 0603  [0603C]  (hidden comment: 4.7uF)
C19  0.1uF,50V,0603  [0603C]
C20  封装: 0402  [0402C]  (hidden comment: 6.2pF,±0.25PF)
C21  封装: 0402  [0402C]  (hidden comment: 6.2pF,±0.25PF)
C22  15pF,50V,0603  [0603C]
C23  0.1uF,50V,0603  [0603C]
C24  封装: 0603  [0603C]  (hidden comment: 16V,TDK,1uF)
C25  15pF,50V,0603  [0603C]
D5  1N4148  [SOD-323]
J2  2.5-3T,180°  [CON250P580W100D50S-3DIP]
J3  2.5-2T,180°  [CON250P580W100D50S-2DIP]
J4  2.5-2T,180°  [CON250P580W100D50S-2DIP]
J5  PWR_ANT  [SIP-3-2.54]
J6  CON2  [SIP-2-2.54]
J7  SWD  [SIP-5-2.54-6.0-R90]
J8  CON2  [SIP-2-2.54]
R12  封装: 0603  [0603R]  (hidden comment: 0Ω)
R13  封装: 0603  [0603R]  (hidden comment: 0Ω)
R14  封装: 0603  [0603R]  (hidden comment: 10KΩ,±1%)
R15  封装: 0603  [0603R]  (hidden comment: 0Ω)
R16  1KΩ,±0.5%,0603  [0603R]
R17  封装: 0603  [0603R]  (hidden comment: 10KΩ,±1%)
S1  6×6×5.0mm  [KEY-6S]
T5  ANT-TX1  [PAD-40]  (no BOM)
T6  ANT-TX2  [PAD-40]  (no BOM)
U3  ZSN700 S0.00  [ZSN700 S0.00]
X1  封装: SMD3225  型号: 12MHz,±10ppm,10pF  [OSCCC250X320X80-4N]  (hidden comment: JYD3A1C7G6-10-12.000,12.0000MHz)
X2  封装: SMD2012  型号: 32.768kHz,12.5pF,±20ppm  [XTAL205X120X60-2N]  (hidden comment: SC-20S,32.768kHz)

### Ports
3.3V_ZSN700 (in), 5V_ZSN700 (in), GND, PA00, PA01, PA02, PA03, PA04, PA08, PA09, PA10, PA11, PA12, PB00, PB01, PB02, PB03, PB04, PB05, PB06, PB07, PB08, PB09, PB10, PB11, PB12, PB13, PB14, PB15, PC00, PC01, PC02, PC03, PC04, PC05, PC06, PC07, PC08, PC09, PC10, PC11, PC12, PC13, PD02, PF06, PF07, TX_ANT8 (out)

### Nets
3.3V_ZSN700: C14.1 C15.1 C16.1 C17.1 C18.1 D5.2 J5.3 J7.1 R14.2 R16.2 U3.22(VDD) U3.30(VDD) U3.41(VDDA) U3.54(VCC33) ; port 3.3V_ZSN700  [project net 3.3V]
5V_ZSN700: J5.1 ; port 5V_ZSN700  [project net 5.0V_Aworks]
GND: C14.2 C15.2 C16.2 C17.2 C18.2 C19.2 C20.1 C21.2 C22.2 C23.2 C24.2 C25.2 J2.2 J3.1 J4.1 J7.5 R17.1 S1.2 S1.3 U3.8(GND) U3.21(GND) U3.29(GND) U3.40(AVSS) U3.58(GND) U3.62(GND) X1.2(GND) X1.4(GND) ; port GND
VCC_ANT: J5.2 U3.59(VCC_ANT)
ANT_TX1: T5.1 U3.57(ANT_TX1)
ANT_TX2: T6.1 U3.60(ANT_TX2)
BOOT0: J8.2 R17.2 U3.26(PF11/BOOT0)
CZ_RX: J2.1 U3.55(CZ_RX)
CZ_TX1: J2.3 J4.2 R12.1 U3.56(CZ_TX1)
CZ_TX2: J3.2 R13.1 U3.61(CZ_TX2)
NRST: C19.1 D5.1 R14.1 R15.1 U3.37(NRST)
PA00: U3.44(PA0) ; port PA00  [project net MicroPort_CTS]
PA01: U3.45(PA1) ; port PA01  [project net MicroPort_RTS]
PA02: U3.46(PA2) ; port PA02  [project net MicroPort_TXD]
PA03: U3.47(PA3) ; port PA03  [project net MicroPort_RXD]
PA04: U3.14(PA4) ; port PA04  [project net MicroPort_DAC]
PA08: U3.68(PA8) ; port PA08  [project net GPIO4_Aworks]
PA09: U3.1(PA9) ; port PA09  [project net I2C0_SCL_Aworks]
PA10: U3.2(PA10) ; port PA10  [project net I2C0_SDA_Aworks]
PA11: U3.3(PA11) ; port PA11  [project net COM2]
PA12: U3.4(PA12) ; port PA12  [project net COM3]
PB00: U3.52(PB0) ; port PB00  [project net MicroPort_PWM2]
PB01: U3.53(PB1) ; port PB01  [project net MicroPort_PWM3]
PB02: U3.63(PB2) ; port PB02  [project net AM4051_ENn]
PB03: U3.19(PB3) ; port PB03  [project net AM4051_S3]
PB04: U3.20(PB4) ; port PB04  [project net AM4051_S2]
PB05: U3.23(PB5) ; port PB05  [project net AM4051_S1]
PB06: U3.24(PB6) ; port PB06  [project net MiniPort_I/O6]
PB07: U3.25(PB7) ; port PB07  [project net MiniPort_I/O7]
PB08: U3.27(PB8) ; port PB08
PB09: U3.28(PB9) ; port PB09
PB10: U3.49(PB10) ; port PB10  [project net MicroPort_PWM0]
PB11: U3.48(PB11) ; port PB11  [project net MicroPort_PWM1]
PB12: U3.9(PB12) ; port PB12  [project net MicroPort_CS]
PB13: U3.10(PB13) ; port PB13  [project net MicroPort_SCK]
PB14: U3.11(PB14) ; port PB14  [project net MicroPort_MISO]
PB15: U3.12(PB15) ; port PB15  [project net MicroPort_MOSI]
PC00: U3.38(PC0) ; port PC00  [project net ADC2_Aworks]
PC01: U3.39(PC1) ; port PC01  [project net ADC3_Aworks]
PC02: U3.42(PC2) ; port PC02  [project net MiniPort_I/O4]
PC03: U3.43(PC3) ; port PC03  [project net MiniPort_I/O5]
PC04: U3.50(PC4) ; port PC04  [project net ADC0_Aworks]
PC05: U3.51(PC5) ; port PC05  [project net ADC1_Aworks]
PC06: U3.64(PC6) ; port PC06  [project net GPIO8_Aworks]
PC07: U3.65(PC7) ; port PC07  [project net GPIO7_Aworks]
PC08: U3.66(PC8) ; port PC08  [project net GPIO6_Aworks]
PC09: U3.67(PC9) ; port PC09  [project net GPIO5_Aworks]
PC10: U3.17(PC10) ; port PC10  [project net COM0]
PC11: U3.15(PC11) ; port PC11  [project net COM1]
PC12: U3.16(PC12) ; port PC12  [project net GPIO11_Aworks]
PC13: U3.32(PC13) ; port PC13
PD02: U3.18(PD2) ; port PD02
PF06: U3.6(PF6) ; port PF06  [project net GPIO_LED0]
PF07: U3.7(PF7) ; port PF07  [project net GPIO_LED1]
RESETB: J6.1 J7.4 R15.2
SWCLK: J7.3 U3.13(PA14)
SWDIO: J7.2 U3.5(PA13)
TX_ANT8: R12.2 R13.2 ; port TX_ANT8  [project net AM4051_TX]
VCAP: C23.1 C24.1 U3.31(VCAP)
XTHI: C20.2 U3.35(PF0/XTHI) X1.1(X1)
XTHO: C21.1 U3.36(PF1/XTHO) X1.3(X2)
XTLI: C22.1 U3.33(PC14/XTLI) X2.2
XTLO: C25.1 U3.34(PC15/XTLO) X2.1
NetJ6_2: J6.2 S1.1 S1.4
NetJ8_1: J8.1 R16.1

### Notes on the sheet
- (1) ZSN700最小系统
- (2)ANT
- RX
  GND
  TX1
- (near J3) GND
  TX2
- (near J4) J4，J5做兼容封装。
- (near J5) 3V3_ANT
  VCC_ANT
  5V_ANT
- (near R13) 单天线和8天线选择
- (near J5) 天线供电电源选择
- (3)复位和调试
- (near J7) 3.3V
- (near J7) SWDIO
- (near J7) SWCLK
- RST
- (near S1) RST
- (near S1) S1
- (near J7) RST
- (near J7) GND
- (4)系统时钟
- (5)RTC时钟
- (near J8) BOOT0

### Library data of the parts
C14-C17 C19 C23 = 02.01.00015: C1608X7R1H104KT000N,0603,TDK,0.1uF,X7R,±10%,50V,; 旧物料代码: 1.02.01.0072; 名称: 电容; 封装: 0603; 贴片和直插: SMT; PCB备注: 151110lmd; 器件优选方案: 推荐使用
C18 = 1.02.01.0080: GRM188R61A475KE15D,4.7uF,±10%,10V,X5R,0603,muRata,RoHS; 名称: 电容; 贴片和直插: SMT; PCB备注: 160602yjh; 器件优选方案: 正常状态，可以选用
C20 C21 = 1.02.17.0094: GRM1555C1H6R2CA01D 6.2pF,±0.25PF,50V,C0G,0402,muRata,RoHS; 名称: 电容; 贴片和直插: SMT; PCB备注: 无数据手册，依据采购部提供的信息添加的封装。; 器件优选方案: 正常状态，可以选用
C22 C25 = 02.01.00106: GRM1885C1H180JA01D,0603,MURATA,15pF,COG,±5%,50V,; 旧物料代码: 1.02.01.0002; 名称: 电容; 封装: 0603; 贴片和直插: SMT; 器件优选方案: 不推荐使用
C24 = 02.01.00365: CGA3E1X7R1C105KT0Y0N,1uF,±10%,16V,X7R,0603,TDK,; 旧物料代码: 1.02.01.0091; 名称: 电容; 贴片和直插: SMT; PCB备注: 180312ZW; 器件优选方案: 推荐使用
D5 = 1.04.07.0027: 1N4148,SOD-323,长电,RoHS; 名称: 二极管; 设备封装名称: SOD-323_1N4148; 贴片和直插: SMT; 器件优选方案: 正常状态，可以选用
J2 = 1.10.06.0010: 2.5-3T,180°,PA46本色,WF2501-WSH03T02,WCON,RoHS; 名称: 插座; 贴片和直插: THT; PCB备注: xhm-lq-wyy-150123 / 150918mxz; 器件优选方案: 正常状态，可以选用
J3 J4 = 1.10.06.0009: 2.5-2T,180°,PA46本色,WF2501-WSH02T02,WCON,RoHS; 名称: 插座; 贴片和直插: THT; PCB备注: xhm-lq-wyy-150123 / 150918mxz; 器件优选方案: 正常状态，可以选用
J5 = CON3: Connector
J6 J8 = CON2: Connector
J7 = CON5: Connector
R12 R13 R15 = 1.01.01.0001: as R56 on sheet 06. Peripheral
R14 R17 = 1.01.01.0052: 10KΩ,±1%,0603,*,RoHS; 名称: 电阻; 设备封装名称: R0603_10K_1%; 厂商: Ralec; 贴片和直插: SMT; 器件优选方案: 正常状态，可以选用
R16 = 01.01.00021: RTT031001DTP,0603,RALEC,1KΩ,±0.5%,1/10W; 旧物料代码: 1.01.01.0095; 名称: 电阻; 封装: 0603; 贴片和直插: SMT; 器件优选方案: 通用物料
S1 = 1.09.01.0003: TS0641-0501B,6×6×5.0mm,黑色,SMD,卷带装,RoHS; 名称: 轻触开关; 贴片和直插: SMT; 器件优选方案: 正常状态，可以选用
T5 T6 = TEST-DOT
U3 = 78.59.00018: 名称: 集成电路; 厂商: ZHIYUAN; 贴片和直插: SMT; PCB备注: 200310hcj; 器件优选方案: 待导入物料
X1 = 1.07.01.0032: JYD3A1C7G6-10-12.000,12.0000MHz,±10ppm,10pF,-40~85℃,±10ppm,SMD3225,*,JYEG,RoHS; 名称: 晶体; 贴片和直插: SMT; PCB备注: 151229lmd171128ZW; 器件优选方案: 正常状态，可以选用
X2 = 1.07.01.0071: SC-20S,32.768kHz,12.5pF,±20ppm,SMD2012,SII; 名称: 晶体(临时); 贴片和直插: SMT; PCB备注: 180227ZW; 器件优选方案: 临时/偏门物料/不主推物料，谨慎选用

## Sheet 02. POWER.SchDoc
size A3; CheckedBy: <审核日期>; Author: 伍伟业; CompanyName: 广州立功科技股份有限公司; DocumentNumber: 2; SheetNumber: 10; SheetTotal: 2; PageSetup: Record=PageOptions¦CenterHorizontal=True¦CenterVertical=True¦PrintScale=1.00¦XCorrection=1.00¦YCorrection=1.00¦PrintKind=0¦BorderSize=5000000¦LeftOffset=0¦BottomOffset=0¦Orientation=2¦PaperLength=1000¦PaperWidth=1000¦Scale=100¦PaperSource=7¦PrintQuality=600¦MediaType=1¦DitherType=10¦PaperKind=A4¦PrintScaleMode=1; DesignDate: 2020-02-25; CheckDate: <审核人员>; SheetName: POWER; SheetVersion: V1.0; SheetDescription: 电源电路
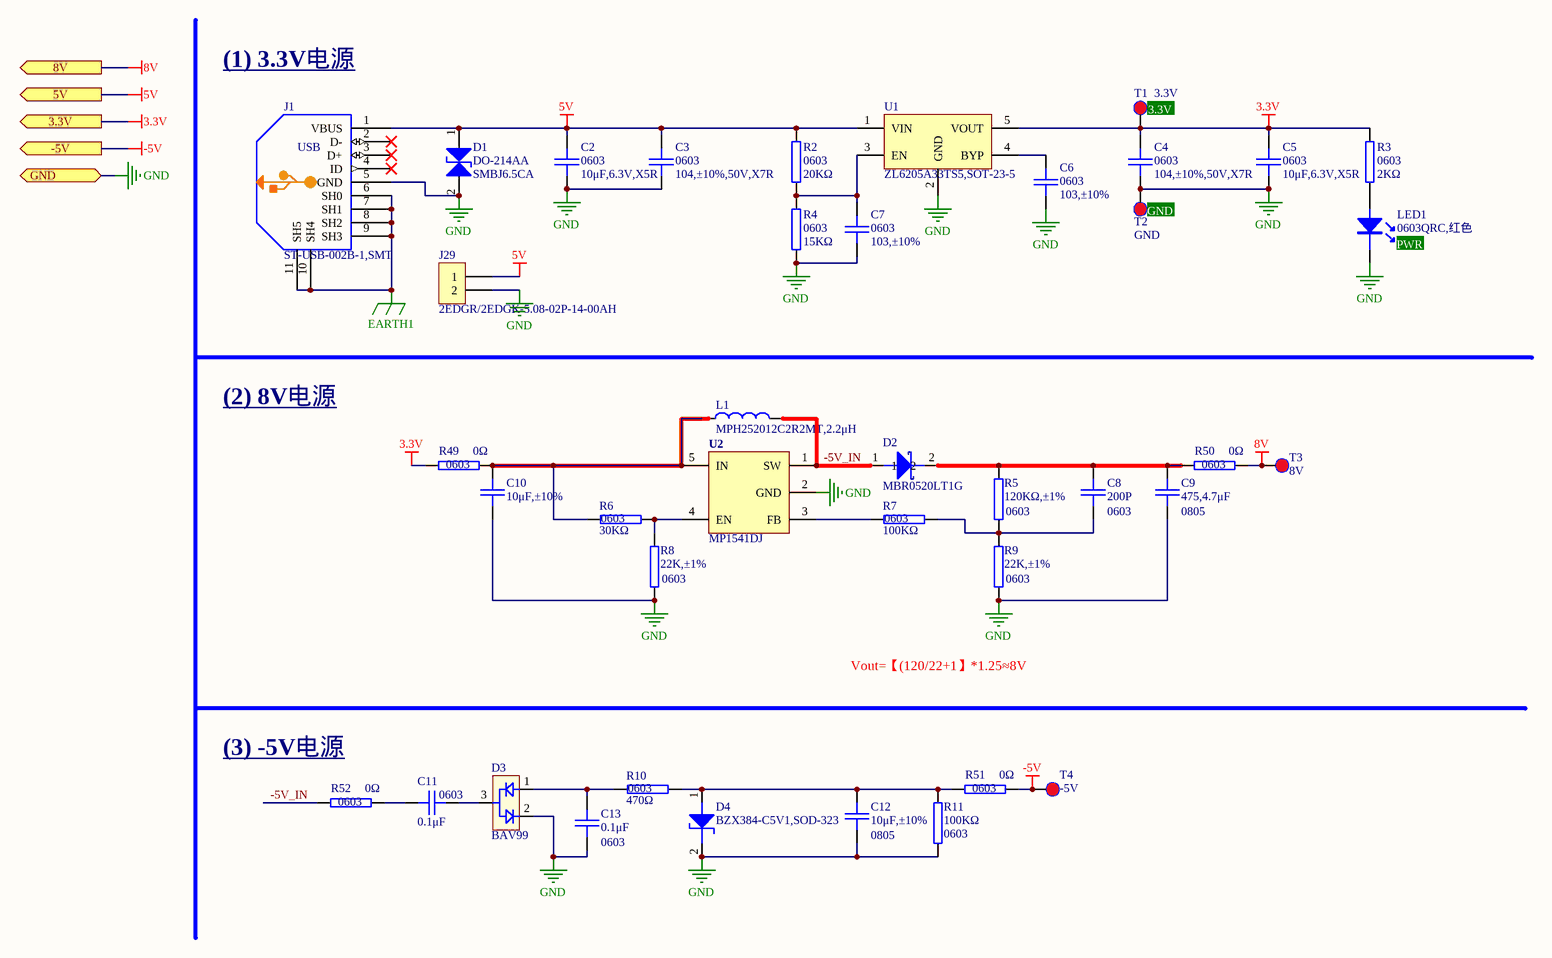
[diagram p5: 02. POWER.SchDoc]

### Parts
C2  封装: 0603  型号: 10μF,6.3V,X5R  [0603C]  (hidden comment: 10μF,6.3V)
C3  封装: 0603  型号: 104,±10%,50V,X7R  [0603C]  (hidden comment: C1608X7R1H104KT000N，104)
C4  封装: 0603  型号: 104,±10%,50V,X7R  [0603C]  (hidden comment: C1608X7R1H104KT000N，104)
C5  封装: 0603  型号: 10μF,6.3V,X5R  [0603C]  (hidden comment: 10μF,6.3V)
C6  封装: 0603  [0603C]  (hidden comment: 103,±10%)
C7  封装: 0603  [0603C]  (hidden comment: 103,±10%)
C8  封装: 0603  [0603C]  (hidden comment: 200P)
C9  封装: 0805  [0805C]  (hidden comment: 475,4.7μF)
C10  10μF,±10%  [0805C]
C11  封装: 0603  [0603C]  (hidden comment: 0.1μF)
C12  封装: 0805  [0805C]  (hidden comment: 10μF,±10%)
C13  封装: 0603  [0603C]  (hidden comment: 0.1μF)
D1  封装: DO-214AA  [SOD-1812]  (hidden comment: SMBJ6.5CA)
D2  MBR0520LT1G  [SOD-123]
D3  BAV99  [SOT-23]
D4  BZX384-C5V1,SOD-323  [SOD-323]
J1  ST-USB-002B-1,SMT  [MICROUSB-ST-USB-002B-1]
J29  2EDGR/2EDGK-5.08-02P-14-00AH  [CON508P1210W160D445S-2RA]
L1  MPH252012C2R2MT,2.2μH  [INDC2520X10N]
LED1  0603QRC,红色  [LED-0603]
R2  封装: 0603  [0603R]  (hidden comment: 20KΩ)
R3  封装: 0603  [0603R]  (hidden comment: 2KΩ)
R4  封装: 0603  [0603R]  (hidden comment: 15KΩ)
R5  封装: 0603  [0603R]  (hidden comment: 120KΩ,±1%)
R6  封装: 0603  [0603R]  (hidden comment: 30KΩ)
R7  封装: 0603  [0603R]  (hidden comment: 100KΩ)
R8  封装: 0603  [0603R]  (hidden comment: 22K,±1%)
R9  封装: 0603  [0603R]  (hidden comment: 22K,±1%)
R10  封装: 0603  [0603R]  (hidden comment: 470Ω)
R11  封装: 0603  [0603R]  (hidden comment: 100KΩ)
R49  封装: 0603  [0603R]  (hidden comment: 0Ω)
R50  封装: 0603  [0603R]  (hidden comment: 0Ω)
R51  封装: 0603  [0603R]  (hidden comment: 0Ω)
R52  封装: 0603  [0603R]  (hidden comment: 0Ω)
T1  3.3V  [PAD-40]  (no BOM)
T2  GND  [PAD-40]  (no BOM)
T3  8V  [PAD-40]  (no BOM)
T4  -5V  [PAD-40]  (no BOM)
U1  ZL6205A33TS5,SOT-23-5  [SOT-23-5]
U2  MP1541DJ  [SOT-23-5]

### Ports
3.3V (out), 5V (out), 8V (out), -5V (out), GND

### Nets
3.3V: C4.2 C5.2 R3.2 R49.1 T1.1 U1.5(VOUT) ; port 3.3V
5V: C2.2 C3.2 D1.1(A) J1.1(VBUS) J29.1 R2.1 U1.1(VIN) ; port 5V  [project net 5.0V_Aworks]
8V: R50.2 T3.1 ; port 8V
-5V: R51.2 T4.1 ; port -5V
EARTH1: J1.6(SH0) J1.7(SH1) J1.8(SH2) J1.9(SH3) J1.10(SH4) J1.11(SH5)
GND: C2.1 C3.1 C4.1 C5.1 C6.1 C7.1 C9.2 C10.2 C12.2 C13.1 D1.2(K) D3.2(D2) D4.2(K) J1.5(GND) J29.2 LED1.2 R4.2 R8.1 R9.1 R11.1 T2.1 U1.2(GND) U2.2(GND) ; port GND
-5V_IN: D2.1 L1.2 R52.1 U2.1(SW)
NetC6_2: C6.2 U1.4(BYP)
NetC7_2: C7.2 R2.2 R4.1 U1.3(EN)
NetC8_1: C8.1 C9.1 D2.2 R5.2 R50.1
NetC8_2: C8.2 R5.1 R7.1 R9.2
NetC10_1: C10.1 L1.1 R6.2 R49.2 U2.5(IN)
NetC11_1: C11.1 R52.2
NetC11_2: C11.2 D3.3(A)
NetC12_1: C12.1 D4.1(A) R10.2 R11.2 R51.1
NetC13_2: C13.2 D3.1(D1) R10.1
NetLED1_1: LED1.1 R3.1
NetR6_1: R6.1 R8.2 U2.4(EN)
NetR7_2: R7.2 U2.3(FB)

Not connected (* = marked no-connect by the designer): J1 2(D-)* 3(D+)* 4(ID)*

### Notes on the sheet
- (1) 3.3V电源
- (near T1) 3.3V
- (near T2) GND
- (near LED1) PWR
- (2) 8V电源
- Vout=【(120/22+1】*1.25≈8V
- (near R52) (3) -5V电源

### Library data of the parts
C2 C5 = 1.02.01.0065: 10μF,6.3V,X5R,GRM188R60J106M****,0603,Murata,RoHS; 名称: 电容; 贴片和直插: SMT; 器件优选方案: 正常状态，可以选用
C3 C4 = 1.02.01.0072: as C30 on sheet 06. Peripheral
C6 C7 = 1.02.01.0090: 103,±10%,50V,X7R,0603,GCM188R71H103KA15D,0603,muRata,ROHS; 名称: 电容; 贴片和直插: SMT; PCB备注: 180305ZW; 器件优选方案: 正常状态，可以选用
C8 = 1.02.01.0015: GRM1885C1H201JA01D,200P,±5%,50V,COG,0603,muRata,RoHS; 名称: 电容; 贴片和直插: SMT; 器件优选方案: 正常状态，可以选用; 设备封装名称: C0603_200P_COG_50V_5%
C9 = 1.02.02.0086: GRM21BR71C475KA73L,475,4.7μF,±10%,16V,X7R,0805,murata,RoHS; 名称: 电容; 贴片和直插: SMT; 器件优选方案: 正常状态，可以选用; PCB备注: 160216lmd
C10 = 1.02.02.0117: 10μF,±10%,10V,X7R,GRM21BR71A106KE51L,0805,muRata,RoHS; 名称: 电容; 封装: 0805; 贴片和直插: SMT; PCB备注: 171017lmd; 器件优选方案: 正常状态，可以选用
C11 C13 = 1.02.01.0032: GRM188R71H104KA93D,104,±10%,50V,X7R,0603,muRata,RoHS; 名称: 电容; 贴片和直插: SMT; 器件优选方案: 临时/偏门物料/不主推物料，谨慎选用; 设备封装名称: C0603_104_X7R_50V_10%
C12 = 1.02.02.0117: 10μF,±10%,10V,X7R,GRM21BR71A106KE51L,0805,muRata,RoHS; 名称: 电容; 贴片和直插: SMT; 器件优选方案: 正常状态，可以选用; PCB备注: 171017lmd
D1 = 1.04.03.0003: SMBJ6.5CA,DO-214AA,君耀,RoHS; 名称: TVS瞬态抑制二极管; 设备封装名称: DO-214AA_SMBJ6.5CA; 贴片和直插: SMT; 器件优选方案: 正常状态，可以选用
D2 = 1.04.07.0014: MBR0520LT1G,SOD-123,ON,RoHS; 名称: 二极管; 设备封装名称: SOD-123_MBR0520; 贴片和直插: SMT; 器件优选方案: 正常状态，可以选用
D3 = 1.04.07.0010: BAV99,SOT-23,NXP,RoHS; 名称: 二极管; 设备封装名称: SOT-23_BAV99; 贴片和直插: SMT; 器件优选方案: 正常状态，可以选用
D4 = 04.03.00033: BZX384-C5V1,SOD-323,NEXPERIA,; 旧物料代码: 1.04.01.0017; 名称: 二极管; 贴片和直插: SMT; 器件优选方案: 通用物料
J1 = 20.02.00033: ST-USB-002B-1,SMT,SUNGTECH,MicroUSB-A; 名称: 连接器; PCB备注: 190710lmd; 器件优选方案: 通用物料
J29 = 1.10.06.0027: 2EDGR/2EDGK-5.08-02P-14-00AH,DEGSON,RoHS; 名称: 端子; 贴片和直插: THT; PCB备注: xhm-lq-wyy-150126; 器件优选方案: 正常状态，可以选用
L1 = 1.03.01.0347: MPH252012C2R2MT,2.2μH,±20%,700mA,1008,Sunlord,RoHs; 名称: 电感; 贴片和直插: SMT; 器件优选方案: 正常状态，可以选用; 封装: 1008; PCB备注: 160722ZW   160729toPCB-hcj
LED1 = 1.04.05.0008: 0603QRC,红色,0603,创光,RoHS; 名称: 发光二极管; 封装: 0603; 设备封装名称: LED0603-RED; 贴片和直插: SMT; 器件优选方案: 正常状态，可以选用
R2 = 1.01.01.0056: 20KΩ,0603,*,RoHS; 名称: 电阻; 设备封装名称: R0603_20K; 厂商: Ralec; 贴片和直插: SMT; 器件优选方案: 正常状态，可以选用
R3 = 1.01.01.0038: 2KΩ,0603,*,RoHS; 名称: 电阻; 设备封装名称: R0603_2K; 厂商: Ralec; 贴片和直插: SMT; 器件优选方案: 正常状态，可以选用
R4 = 1.01.01.0054: 15KΩ,0603,*,RoHS; 名称: 电阻; 设备封装名称: R0603_15K; 厂商: Ralec; 贴片和直插: SMT; 器件优选方案: 正常状态，可以选用
R5 = 1.01.01.0064: 120KΩ,±1%,0603,*,RoHS; 名称: 电阻; 厂商: Ralec; 贴片和直插: SMT; 器件优选方案: 正常状态，可以选用; 设备封装名称: R0603_120K_1%
R6 = 1.01.01.0058: 30KΩ,0603,*,RoHS; 名称: 电阻; 设备封装名称: R0603_30K; 厂商: Ralec; 贴片和直插: SMT; 器件优选方案: 正常状态，可以选用
R7 R11 = 1.01.01.0062: 100KΩ,0603,*,RoHS; 名称: 电阻; 设备封装名称: R0603_100K; 厂商: Ralec; 贴片和直插: SMT; 器件优选方案: 正常状态，可以选用
R8 R9 = 1.01.01.0152: 22K,±1%,0603,RoHS; 名称: 电阻; 厂商: Ralec; 贴片和直插: SMT; 器件优选方案: 正常状态，可以选用; 设备封装名称: R0603_22K_1%
R10 = 1.01.01.0032: 470Ω,0603,*,RoHS; 名称: 电阻; 设备封装名称: R0603_470R; 厂商: Ralec; 贴片和直插: SMT; 器件优选方案: 正常状态，可以选用
R49-R52 = 1.01.01.0001: as R56 on sheet 06. Peripheral
T1-T4 = TEST-DOT
U1 = 08.09.03069: ZL6205A33TS5,SOT-23-5,ZLG; 名称: 集成电路; 贴片和直插: SMT; PCB备注: 190806hcj; 器件优选方案: 待导入物料
U2 = 1.05.09.0258: MP1541DJ,TSOT23-5,MPS,RoHS; 名称: 集成电路; 贴片和直插: SMT; PCB备注: 151014mxz; 器件优选方案: 正常状态，可以选用

## Sheet 04. SAM.SchDoc
size A4; CheckedBy: 赵金生; Author: 伍伟业; CompanyName: 广州周立功单片机科技有限公司; DocumentNumber: 4; SheetNumber: 4; SheetTotal: 10; PageSetup: Record=PageOptions¦CenterHorizontal=True¦CenterVertical=True¦PrintScale=1.00¦XCorrection=1.00¦YCorrection=1.00¦PrintKind=0¦BorderSize=5000000¦LeftOffset=0¦BottomOffset=0¦Orientation=2¦PaperLength=1000¦PaperWidth=1000¦Scale=100¦PaperSource=7¦PrintQuality=600¦MediaType=1¦DitherType=10¦PaperKind=A4¦PrintScaleMode=1; DesignDate: 2018-11-26; CheckDate: 2018-11-27; SheetName: SAM; SheetVersion: V1.0; SheetDescription: SAM卡电路
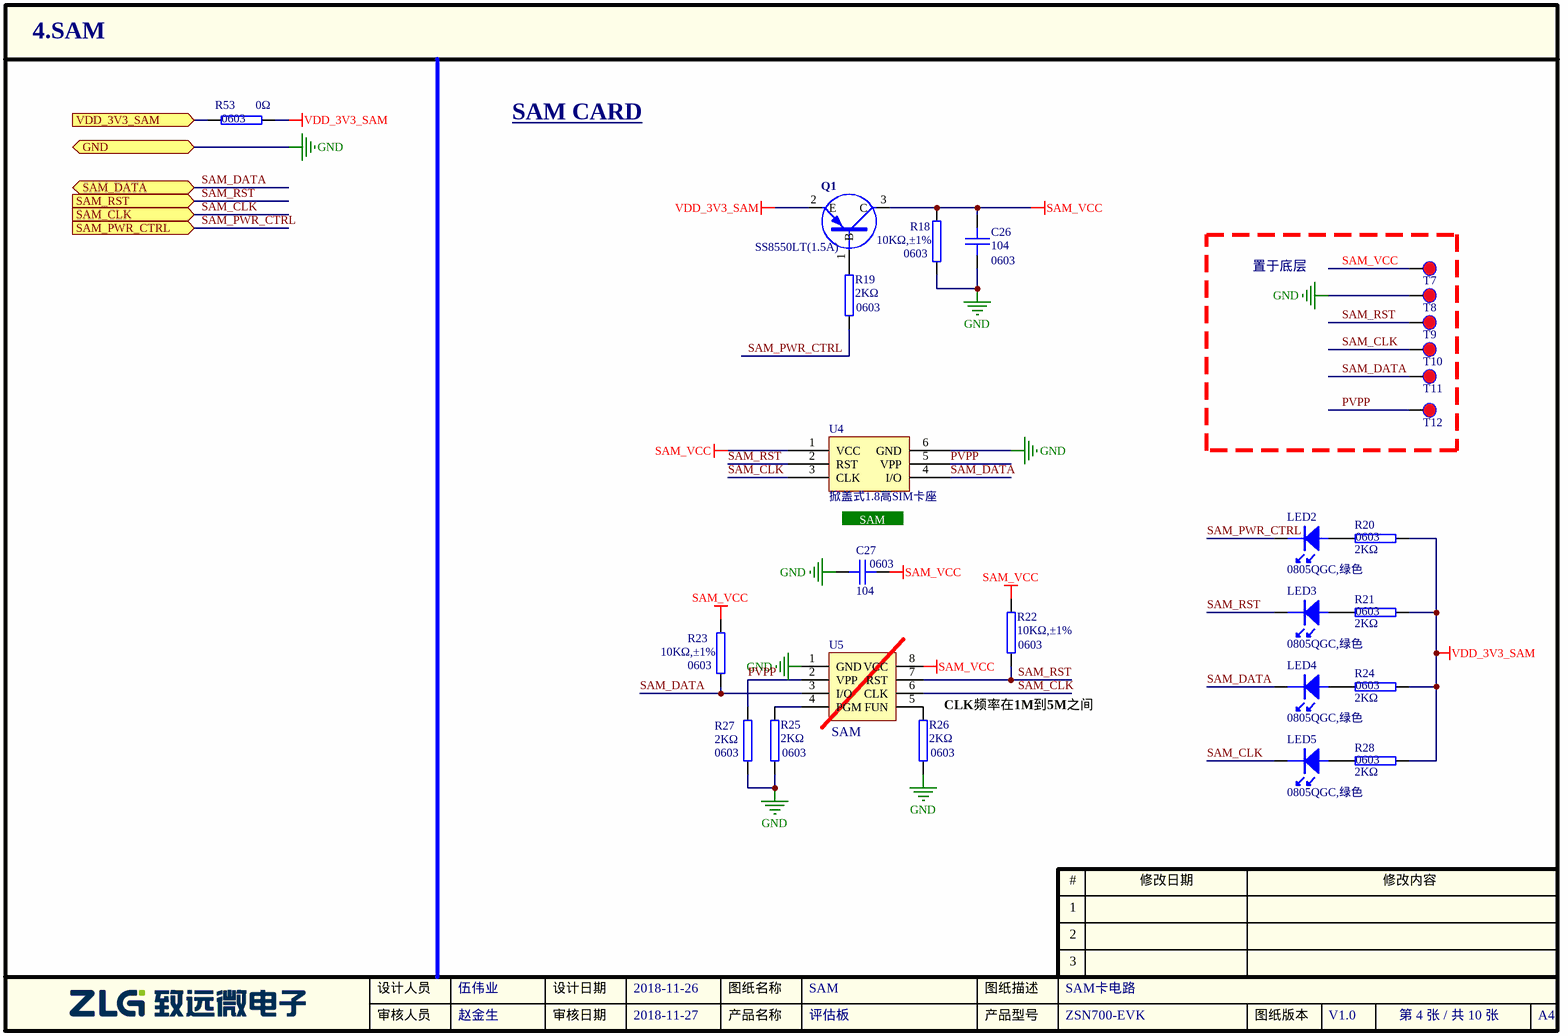
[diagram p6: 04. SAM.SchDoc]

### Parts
C26  封装: 0603  [0603C]  (hidden comment: 104)
C27  封装: 0603  [0603C]  (hidden comment: 104)
LED2  0805QGC,绿色  [LED-0805]
LED3  0805QGC,绿色  [LED-0805]
LED4  0805QGC,绿色  [LED-0805]
LED5  0805QGC,绿色  [LED-0805]
Q1  value SS8550LT(1.5A)  [SOT-23]  (hidden comment: PNP-1)
R18  封装: 0603  [0603R]  (hidden comment: 10KΩ,±1%)
R19  封装: 0603  [0603R]  (hidden comment: 2KΩ)
R20  封装: 0603  [0603R]  (hidden comment: 2KΩ)
R21  封装: 0603  [0603R]  (hidden comment: 2KΩ)
R22  封装: 0603  [0603R]  (hidden comment: 10KΩ,±1%)
R23  封装: 0603  [0603R]  (hidden comment: 10KΩ,±1%)
R24  封装: 0603  [0603R]  (hidden comment: 2KΩ)
R25  封装: 0603  [0603R]  (hidden comment: 2KΩ)
R26  封装: 0603  [0603R]  (hidden comment: 2KΩ)
R27  封装: 0603  [0603R]  (hidden comment: 2KΩ)
R28  封装: 0603  [0603R]  (hidden comment: 2KΩ)
R53  封装: 0603  [0603R]  (hidden comment: 0Ω)
T7  TEST-DOT  [PAD-40]  (value not drawn)  (no BOM)
T8  TEST-DOT  [PAD-40]  (value not drawn)  (no BOM)
T9  TEST-DOT  [PAD-40]  (value not drawn)  (no BOM)
T10  TEST-DOT  [PAD-40]  (value not drawn)  (no BOM)
T11  TEST-DOT  [PAD-40]  (value not drawn)  (no BOM)
T12  TEST-DOT  [PAD-40]  (value not drawn)  (no BOM)
U4  掀盖式1.8高SIM卡座  [SIM-CARD-24.65X17.65-6P]
U5  HEADER 4X2R  [DIP762W62P254L1016H500Q8P]  (value not drawn)

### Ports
GND, SAM_CLK (in), SAM_DATA (bidir), SAM_PWR_CTRL (in), SAM_RST (in), VDD_3V3_SAM (in)

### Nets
3.3V: R53.1 ; port VDD_3V3_SAM
GND: C26.2 C27.2 R18.2 R25.1 R26.1 R27.1 T8.1 U4.6(GND) U5.1(GND) ; port GND
SAM_VCC: C26.1 C27.1 Q1.3(C) R18.1 R22.2 R23.2 T7.1 U4.1(VCC) U5.8(VCC)
VDD_3V3_SAM: Q1.2(E) R20.2 R21.2 R24.2 R28.2 R53.2
PVPP: R27.2 T12.1 U4.5(VPP) U5.2(VPP)
SAM_CLK: LED5.2 T10.1 U4.3(CLK) U5.6(CLK) ; port SAM_CLK  [project net PC13]
SAM_DATA: LED4.2 R23.1 T11.1 U4.4(I/O) U5.3(I/O) ; port SAM_DATA  [project net PB08]
SAM_PWR_CTRL: LED2.2 R19.1 ; port SAM_PWR_CTRL  [project net PD02]
SAM_RST: LED3.2 R22.1 T9.1 U4.2(RST) U5.7(RST) ; port SAM_RST  [project net PB09]
NetLED2_1: LED2.1 R20.1
NetLED3_1: LED3.1 R21.1
NetLED4_1: LED4.1 R24.1
NetLED5_1: LED5.1 R28.1
NetQ1_1: Q1.1(B) R19.2
NetR25_2: R25.2 U5.4(PGM)
NetR26_2: R26.2 U5.5(FUN)

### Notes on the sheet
- SAM CARD
- 置于底层
- SAM
- (near R26) CLK频率在1M到5M之间
- (near U5) SAM

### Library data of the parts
C26 C27 = 1.02.01.0032: GRM188R71H104KA93D,104,±10%,50V,X7R,0603,muRata,RoHS; 名称: 电容; 设备封装名称: C0603_104_X7R_50V_10%; 贴片和直插: SMT; 器件优选方案: 临时/偏门物料/不主推物料，谨慎选用
LED2-LED5 = 1.04.05.0002: 0805QGC,绿色,0805,RoHS; 名称: 发光二极管; 封装: 0805; 设备封装名称: LED0805-GREEN; 贴片和直插: SMT; 器件优选方案: 正常状态，可以选用
Q1 = 1.04.09.0002: SS8550LT(1.5A),SOT-23,江苏长电,RoHS; 名称: 三极管; 设备封装名称: SOT-23_SS8550LT; 贴片和直插: SMT
R18 R22 R23 = 1.01.01.0052: as R14 on sheet 03. ZSN700
R19-R21 R24-R28 = 1.01.01.0038: as R3 on sheet 02. POWER
R53 = 1.01.01.0001: as R56 on sheet 06. Peripheral
U4 = 1.10.17.0012: 名称: SIM卡座; 贴片和直插: SMT; PCB备注: 180227ZW; 器件优选方案: 正常状态，可以选用
U5 = 1.10.02.0001: DIP-8,300mil,,*; 名称: IC座; 贴片和直插: THT; PCB备注: 160128lmd

## Sheet 05. Analog Multiplexer.SchDoc
size A4; CheckedBy: 赵金生; Author: 伍伟业; CompanyName: 广州周立功单片机科技有限公司; DocumentNumber: 5; SheetNumber: 5; SheetTotal: 10; PageSetup: Record=PageOptions¦CenterHorizontal=True¦CenterVertical=True¦PrintScale=1.00¦XCorrection=1.00¦YCorrection=1.00¦PrintKind=0¦BorderSize=5000000¦LeftOffset=0¦BottomOffset=0¦Orientation=2¦PaperLength=1000¦PaperWidth=1000¦Scale=100¦PaperSource=7¦PrintQuality=600¦MediaType=1¦DitherType=10¦PaperKind=A4¦PrintScaleMode=1; DesignDate: 2017-12-22; CheckDate: 2017-12-26; SheetName: Analog Multiplexer; SheetVersion: V1.01; SheetDescription: 模拟开关4051
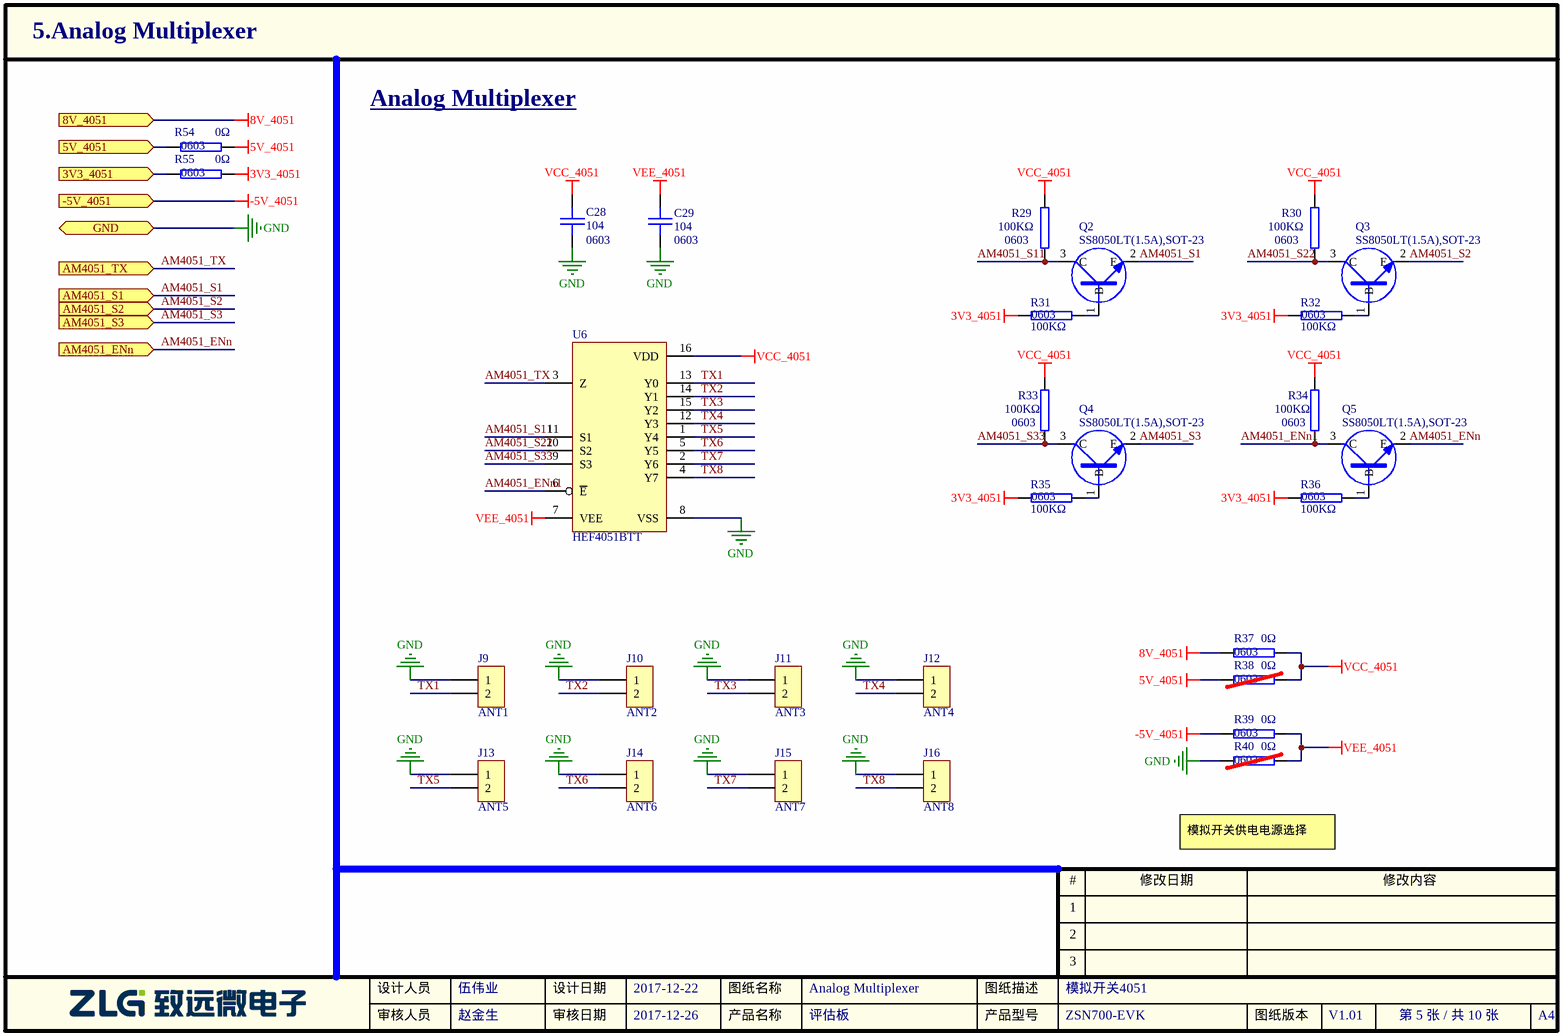
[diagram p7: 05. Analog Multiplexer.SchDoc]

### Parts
C28  封装: 0603  [0603C]  (hidden comment: 104)
C29  封装: 0603  [0603C]  (hidden comment: 104)
J9  ANT1  [CON250P580W100D50S-2DIP]
J10  ANT2  [CON250P580W100D50S-2DIP]
J11  ANT3  [CON250P580W100D50S-2DIP]
J12  ANT4  [CON250P580W100D50S-2DIP]
J13  ANT5  [CON250P580W100D50S-2DIP]
J14  ANT6  [CON250P580W100D50S-2DIP]
J15  ANT7  [CON250P580W100D50S-2DIP]
J16  ANT8  [CON250P580W100D50S-2DIP]
Q2  SS8050LT(1.5A),SOT-23  [SOT-23]
Q3  SS8050LT(1.5A),SOT-23  [SOT-23]
Q4  SS8050LT(1.5A),SOT-23  [SOT-23]
Q5  SS8050LT(1.5A),SOT-23  [SOT-23]
R29  封装: 0603  [0603R]  (hidden comment: 100KΩ)
R30  封装: 0603  [0603R]  (hidden comment: 100KΩ)
R31  封装: 0603  [0603R]  (hidden comment: 100KΩ)
R32  封装: 0603  [0603R]  (hidden comment: 100KΩ)
R33  封装: 0603  [0603R]  (hidden comment: 100KΩ)
R34  封装: 0603  [0603R]  (hidden comment: 100KΩ)
R35  封装: 0603  [0603R]  (hidden comment: 100KΩ)
R36  封装: 0603  [0603R]  (hidden comment: 100KΩ)
R37  封装: 0603  [0603R]  (hidden comment: 0Ω)
R38  封装: 0603  [0603R]  (hidden comment: 0Ω)
R39  封装: 0603  [0603R]  (hidden comment: 0Ω)
R40  封装: 0603  [0603R]  (hidden comment: 0Ω)
R54  封装: 0603  [0603R]  (hidden comment: 0Ω)
R55  封装: 0603  [0603R]  (hidden comment: 0Ω)
U6  HEF4051BTT  [SOP65P640X110-16N]

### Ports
3V3_4051 (in), 5V_4051 (in), 8V_4051 (in), -5V_4051 (in), AM4051_ENn (in), AM4051_S1 (in), AM4051_S2 (in), AM4051_S3 (in), AM4051_TX (in), GND

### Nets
3.3V: R55.1 ; port 3V3_4051
3V3_4051: R31.2 R32.2 R35.2 R36.2 R55.2
5.0V_Aworks: R54.1 ; port 5V_4051
5V_4051: R38.1 R54.2
8V_4051: R37.1 ; port 8V_4051  [project net 8V]
-5V_4051: R39.1 ; port -5V_4051  [project net -5V]
GND: C28.2 C29.2 J9.1 J10.1 J11.1 J12.1 J13.1 J14.1 J15.1 J16.1 R40.1 U6.8(VSS) ; port GND
VCC_4051: C28.1 R29.2 R30.2 R33.2 R34.2 R37.2 R38.2 U6.16(VDD)
VEE_4051: C29.1 R39.2 R40.2 U6.7(VEE)
AM4051_ENn: Q5.2(E) ; port AM4051_ENn
AM4051_ENn1: Q5.3(C) R34.1 U6.6(~{E})
AM4051_S1: Q2.2(E) ; port AM4051_S1
AM4051_S2: Q3.2(E) ; port AM4051_S2
AM4051_S3: Q4.2(E) ; port AM4051_S3
AM4051_S11: Q2.3(C) R29.1 U6.11(S1)
AM4051_S22: Q3.3(C) R30.1 U6.10(S2)
AM4051_S33: Q4.3(C) R33.1 U6.9(S3)
AM4051_TX: U6.3(Z) ; port AM4051_TX
TX1: J9.2 U6.13(Y0)
TX2: J10.2 U6.14(Y1)
TX3: J11.2 U6.15(Y2)
TX4: J12.2 U6.12(Y3)
TX5: J13.2 U6.1(Y4)
TX6: J14.2 U6.5(Y5)
TX7: J15.2 U6.2(Y6)
TX8: J16.2 U6.4(Y7)
NetQ2_1: Q2.1(B) R31.1
NetQ3_1: Q3.1(B) R32.1
NetQ4_1: Q4.1(B) R35.1
NetQ5_1: Q5.1(B) R36.1

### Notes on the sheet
- Analog Multiplexer
- 模拟开关供电电源选择

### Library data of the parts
C28 C29 = 1.02.01.0032: as C11 on sheet 02. POWER
J9-J16 = 1.10.06.0009: as J3 on sheet 03. ZSN700
Q2-Q5 = 1.04.09.0001: SS8050LT(1.5A),SOT-23,长电,RoHS; 名称: 三极管; 设备封装名称: SOT-23_SS8050LT; 型号: SS8050LT(1.5A),SOT-23,江苏长电,RoHS; 贴片和直插: SMT; 器件优选方案: 正常状态，可以选用
R29-R36 = 1.01.01.0062: as R7 on sheet 02. POWER
R37-R40 R54 R55 = 1.01.01.0001: as R56 on sheet 06. Peripheral
U6 = 1.05.10.0716: HEF4051BTT,TSSOP16,Nexperia; 名称: 集成电路; 贴片和直插: SMT; PCB备注: 171228lmd; 器件优选方案: 正常状态，可以选用

## Sheet 10. LCD Port.SchDoc
size A4; CheckedBy: <审核日期>; Author: 伍伟业; CompanyName: 广州立功科技股份有限公司; DocumentNumber: 10; SheetNumber: 10; SheetTotal: 10; PageSetup: Record=PageOptions¦CenterHorizontal=True¦CenterVertical=True¦PrintScale=1.00¦XCorrection=1.00¦YCorrection=1.00¦PrintKind=0¦BorderSize=5000000¦LeftOffset=0¦BottomOffset=0¦Orientation=2¦PaperLength=1000¦PaperWidth=1000¦Scale=100¦PaperSource=7¦PrintQuality=600¦MediaType=1¦DitherType=10¦PaperKind=A4¦PrintScaleMode=1; DesignDate: 2020-02-25; CheckDate: <审核人员>; SheetName: LCD Port; SheetVersion: V1.0; SheetDescription: 段码式显示屏接口
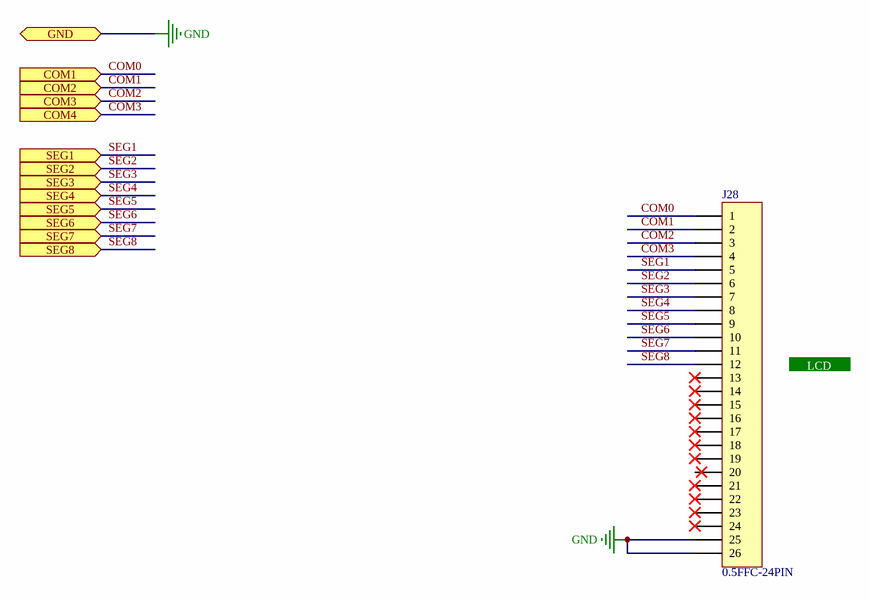
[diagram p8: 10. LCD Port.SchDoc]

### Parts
J28  0.5FFC-24PIN  [FFCF0.5-24P-R0-A]

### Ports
COM1 (in), COM2 (in), COM3 (in), COM4 (in), GND, SEG1 (in), SEG2 (in), SEG3 (in), SEG4 (in), SEG5 (in), SEG6 (in), SEG7 (in), SEG8 (in)

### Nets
GND: J28.25 J28.26 ; port GND
COM0: J28.1 ; port COM1
COM1: J28.2 ; port COM2
COM2: J28.3 ; port COM3
COM3: J28.4 ; port COM4
SEG1: J28.5 ; port SEG1  [project net GPIO4_Aworks]
SEG2: J28.6 ; port SEG2  [project net GPIO5_Aworks]
SEG3: J28.7 ; port SEG3  [project net GPIO6_Aworks]
SEG4: J28.8 ; port SEG4  [project net GPIO7_Aworks]
SEG5: J28.9 ; port SEG5  [project net GPIO8_Aworks]
SEG6: J28.10 ; port SEG6  [project net ADC2_Aworks]
SEG7: J28.11 ; port SEG7  [project net ADC3_Aworks]
SEG8: J28.12 ; port SEG8  [project net GPIO11_Aworks]

Not connected (* = marked no-connect by the designer): J28 13* 14* 15* 16* 17* 18* 19* 20 21* 22* 23* 24*

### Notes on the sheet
- LCD

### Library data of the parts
J28 = 1.10.01.0133: 0.5FFC-24PIN,SMD,*,RoHS; 名称: 连接器; 贴片和直插: SMT; PCB备注: 180118lmd; 器件优选方案: 正常状态，可以选用

## Sheet 09. AworksPort_MCU.SchDoc
size A4; CheckedBy: <审核日期>; Author: 赵金生; CompanyName: 广州周立功单片机科技有限公司; DocumentNumber: 9; SheetNumber: 9; SheetTotal: 10; PageSetup: Record=PageOptions¦CenterHorizontal=True¦CenterVertical=True¦PrintScale=1.00¦XCorrection=1.00¦YCorrection=1.00¦PrintKind=0¦BorderSize=5000000¦LeftOffset=0¦BottomOffset=0¦Orientation=2¦PaperLength=1000¦PaperWidth=1000¦Scale=100¦PaperSource=7¦PrintQuality=600¦MediaType=1¦DitherType=10¦PaperKind=A4¦PrintScaleMode=1; DesignDate: 2017-7-15; CheckDate: <审核人员>; SheetName: AworksPort 主机接口; SheetVersion: V1.01; SheetDescription: ApploPort接口,  Host板适用该图纸，不适用Device板; productModel: AMS32K144-Core; productName: 开发套件
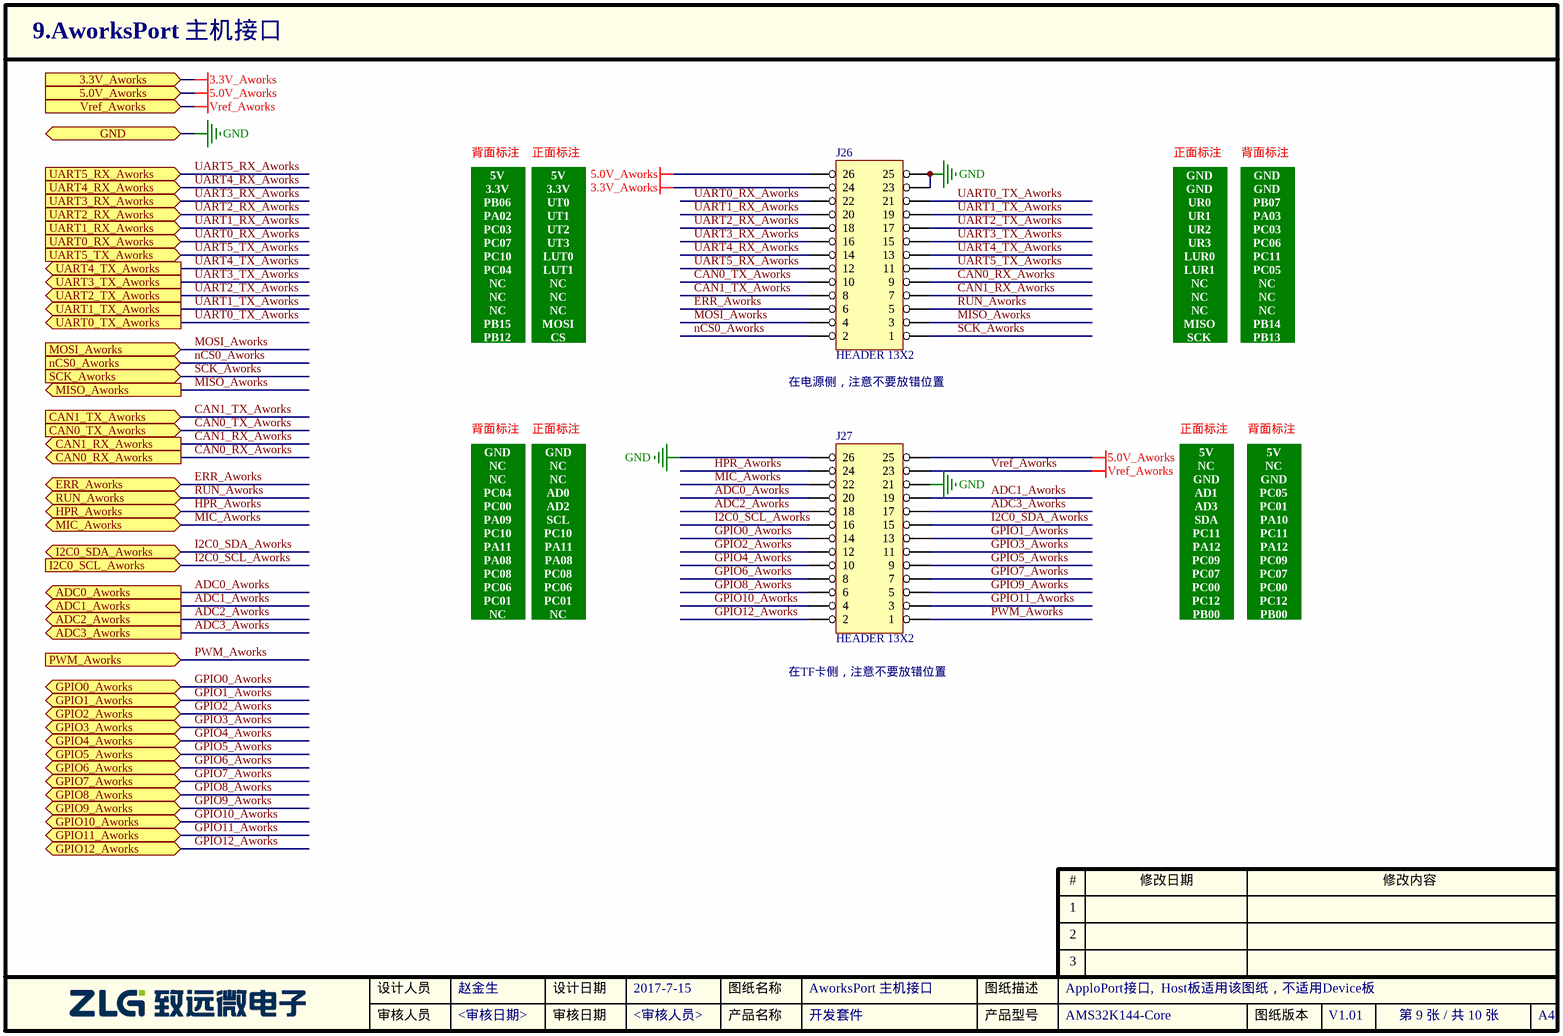
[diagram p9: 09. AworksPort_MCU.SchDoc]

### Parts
J26  HEADER 13X2  [IDC-26-2.54]
J27  HEADER 13X2  [IDC-26-2.54]

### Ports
3.3V_Aworks (in), 5.0V_Aworks (in), ADC0_Aworks (out), ADC1_Aworks (out), ADC2_Aworks (out), ADC3_Aworks (out), CAN0_RX_Aworks (out), CAN0_TX_Aworks (in), CAN1_RX_Aworks (out), CAN1_TX_Aworks (in), ERR_Aworks (bidir), GND, GPIO0_Aworks (bidir), GPIO1_Aworks (bidir), GPIO2_Aworks (bidir), GPIO3_Aworks (bidir), GPIO4_Aworks (bidir), GPIO5_Aworks (bidir), GPIO6_Aworks (bidir), GPIO7_Aworks (bidir), GPIO8_Aworks (bidir), GPIO9_Aworks (bidir), GPIO10_Aworks (bidir), GPIO11_Aworks (bidir), GPIO12_Aworks (bidir), HPR_Aworks (bidir), I2C0_SCL_Aworks (in), I2C0_SDA_Aworks (bidir), MIC_Aworks (bidir), MISO_Aworks (out), MOSI_Aworks (in), nCS0_Aworks (in), PWM_Aworks (in), RUN_Aworks (bidir), SCK_Aworks (in), UART0_RX_Aworks (in), UART0_TX_Aworks (out), UART1_RX_Aworks (in), UART1_TX_Aworks (out), UART2_RX_Aworks (in), UART2_TX_Aworks (out), UART3_RX_Aworks (in), UART3_TX_Aworks (out), UART4_RX_Aworks (in), UART4_TX_Aworks (out), UART5_RX_Aworks (in), UART5_TX_Aworks (in), Vref_Aworks (in)

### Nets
3.3V_Aworks: J26.24 J27.23 ; port 3.3V_Aworks, port Vref_Aworks  [also labelled Vref_Aworks]  [project net 3.3V]
5.0V_Aworks: J26.26 J27.25 ; port 5.0V_Aworks
GND: J26.23 J26.25 J27.21 J27.26 ; port GND
ADC0_Aworks: J26.12 J27.20 ; port UART5_RX_Aworks, port ADC0_Aworks  [also labelled UART5_RX_Aworks]
ADC1_Aworks: J26.11 J27.19 ; port UART5_TX_Aworks, port ADC1_Aworks  [also labelled UART5_TX_Aworks]
ADC2_Aworks: J27.5 J27.18 ; port ADC2_Aworks, port GPIO9_Aworks  [also labelled GPIO9_Aworks]
ADC3_Aworks: J27.4 J27.17 ; port ADC3_Aworks, port GPIO10_Aworks  [also labelled GPIO10_Aworks]
CAN0_RX_Aworks: J26.9 ; port CAN0_RX_Aworks
CAN0_TX_Aworks: J26.10 ; port CAN0_TX_Aworks
CAN1_RX_Aworks: J26.7 ; port CAN1_RX_Aworks
CAN1_TX_Aworks: J26.8 ; port CAN1_TX_Aworks
ERR_Aworks: J26.6 ; port ERR_Aworks
GPIO0_Aworks: J26.14 J27.14 ; port UART4_RX_Aworks, port GPIO0_Aworks  [also labelled UART4_RX_Aworks]  [project net COM0]
GPIO1_Aworks: J26.13 J27.13 ; port UART4_TX_Aworks, port GPIO1_Aworks  [also labelled UART4_TX_Aworks]  [project net COM1]
GPIO2_Aworks: J27.12 ; port GPIO2_Aworks  [project net COM2]
GPIO3_Aworks: J27.11 ; port GPIO3_Aworks  [project net COM3]
GPIO4_Aworks: J27.10 ; port GPIO4_Aworks
GPIO5_Aworks: J27.9 ; port GPIO5_Aworks
GPIO6_Aworks: J27.8 ; port GPIO6_Aworks
GPIO7_Aworks: J26.16 J27.7 ; port UART3_RX_Aworks, port GPIO7_Aworks  [also labelled UART3_RX_Aworks]
GPIO8_Aworks: J26.15 J27.6 ; port UART3_TX_Aworks, port GPIO8_Aworks  [also labelled UART3_TX_Aworks]
GPIO11_Aworks: J27.3 ; port GPIO11_Aworks
GPIO12_Aworks: J27.2 ; port GPIO12_Aworks
HPR_Aworks: J27.24 ; port HPR_Aworks
I2C0_SCL_Aworks: J27.16 ; port I2C0_SCL_Aworks
I2C0_SDA_Aworks: J27.15 ; port I2C0_SDA_Aworks
MIC_Aworks: J27.22 ; port MIC_Aworks
MISO_Aworks: J26.3 ; port MISO_Aworks  [project net MicroPort_MISO]
MOSI_Aworks: J26.4 ; port MOSI_Aworks  [project net MicroPort_MOSI]
nCS0_Aworks: J26.2 ; port nCS0_Aworks  [project net MicroPort_CS]
PWM_Aworks: J27.1 ; port PWM_Aworks  [project net MicroPort_PWM2]
RUN_Aworks: J26.5 ; port RUN_Aworks
SCK_Aworks: J26.1 ; port SCK_Aworks  [project net MicroPort_SCK]
UART0_RX_Aworks: J26.22 ; port UART0_RX_Aworks  [project net MiniPort_I/O6]
UART0_TX_Aworks: J26.21 ; port UART0_TX_Aworks  [project net MiniPort_I/O7]
UART1_RX_Aworks: J26.20 ; port UART1_RX_Aworks  [project net MicroPort_TXD]
UART1_TX_Aworks: J26.19 ; port UART1_TX_Aworks  [project net MicroPort_RXD]
UART2_RX_Aworks: J26.18 ; port UART2_RX_Aworks  [project net MiniPort_I/O5]
UART2_TX_Aworks: J26.17 ; port UART2_TX_Aworks  [project net MiniPort_I/O4]

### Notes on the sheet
- 5V
- 背面标注
- 正面标注
- GND
- PB06
- PC03
- PC07
- PA02
- 3.3V
- UT3
- UT2
- UT1
- UT0
- UR3
- UR2
- UR1
- UR0
- PB07
- PA03
- PC06
- NC
- PC10
- PC04
- LUT0
- LUT1
- LUR0
- LUR1
- PC11
- PC05
- PB15
- PB12
- CS
- MOSI
- (near J26) 在电源侧，注意不要放错位置
- SCK
- MISO
- PB14
- PB13
- PC00
- PA09
- AD0
- AD2
- SCL
- SDA
- AD3
- AD1
- PC01
- PA10
- PC08
- PA08
- PA11
- PC09
- PA12
- PB00
- PC12
- (near J27) 在TF卡侧，注意不要放错位置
